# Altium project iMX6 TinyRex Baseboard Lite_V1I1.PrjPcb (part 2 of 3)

## Sheet [07] - PCIE MINI.SchDoc
size A2; DocumentNumber: 7; SheetNumber: 7; SheetTotal: 18
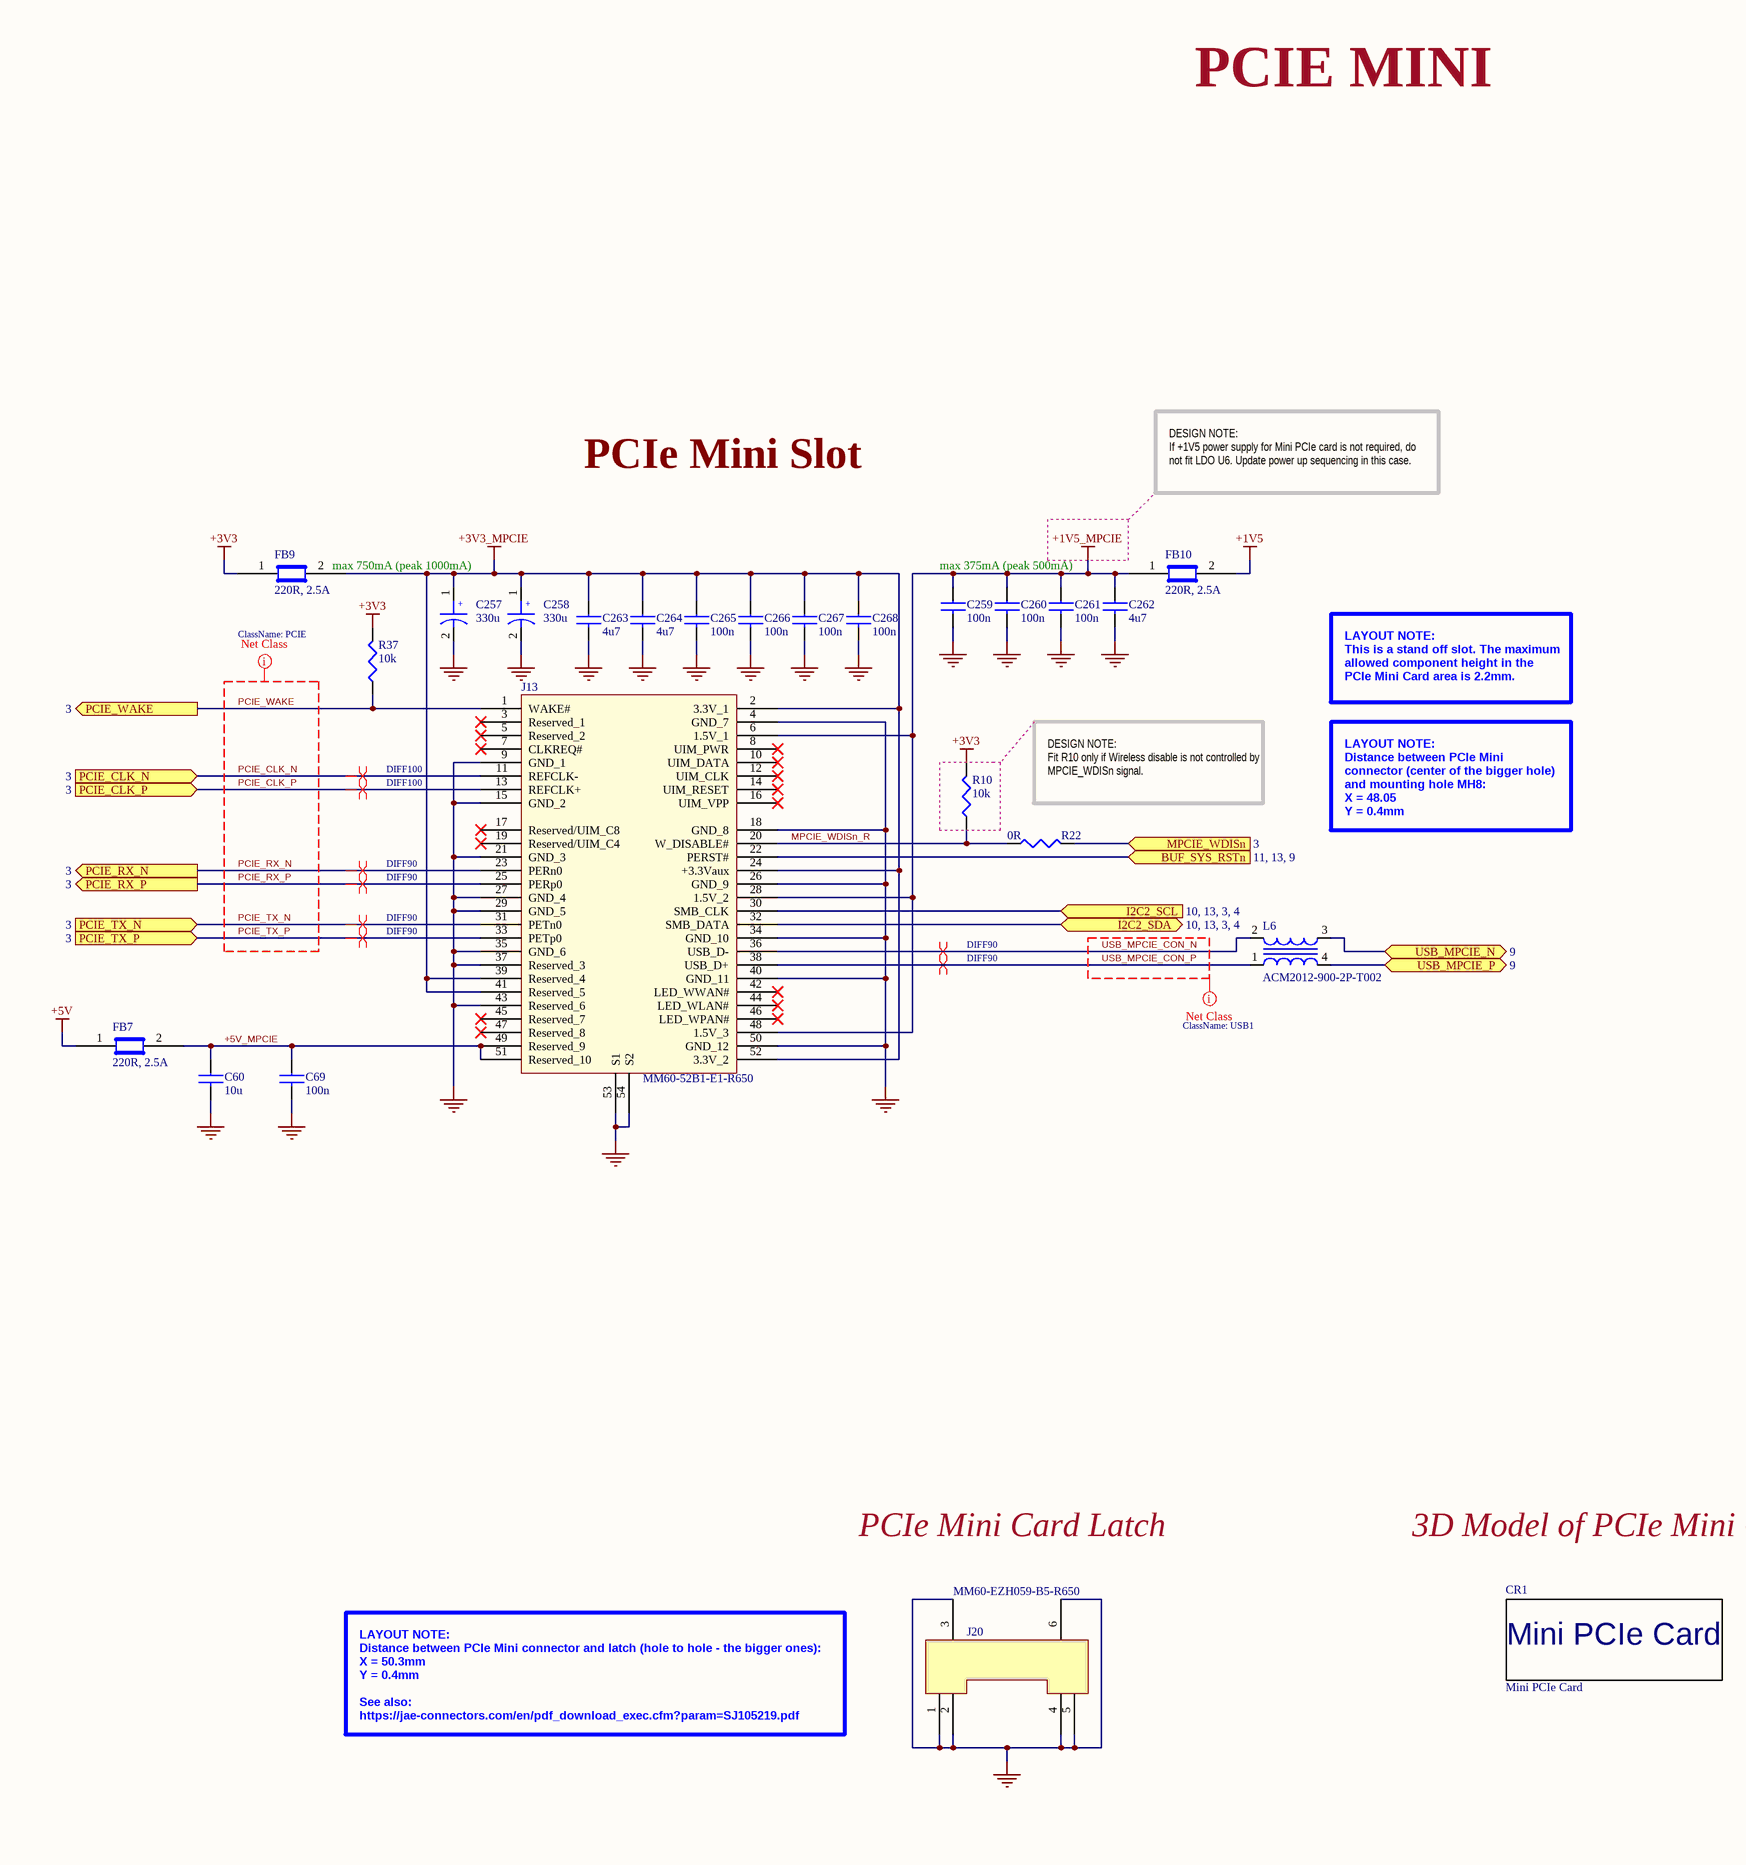
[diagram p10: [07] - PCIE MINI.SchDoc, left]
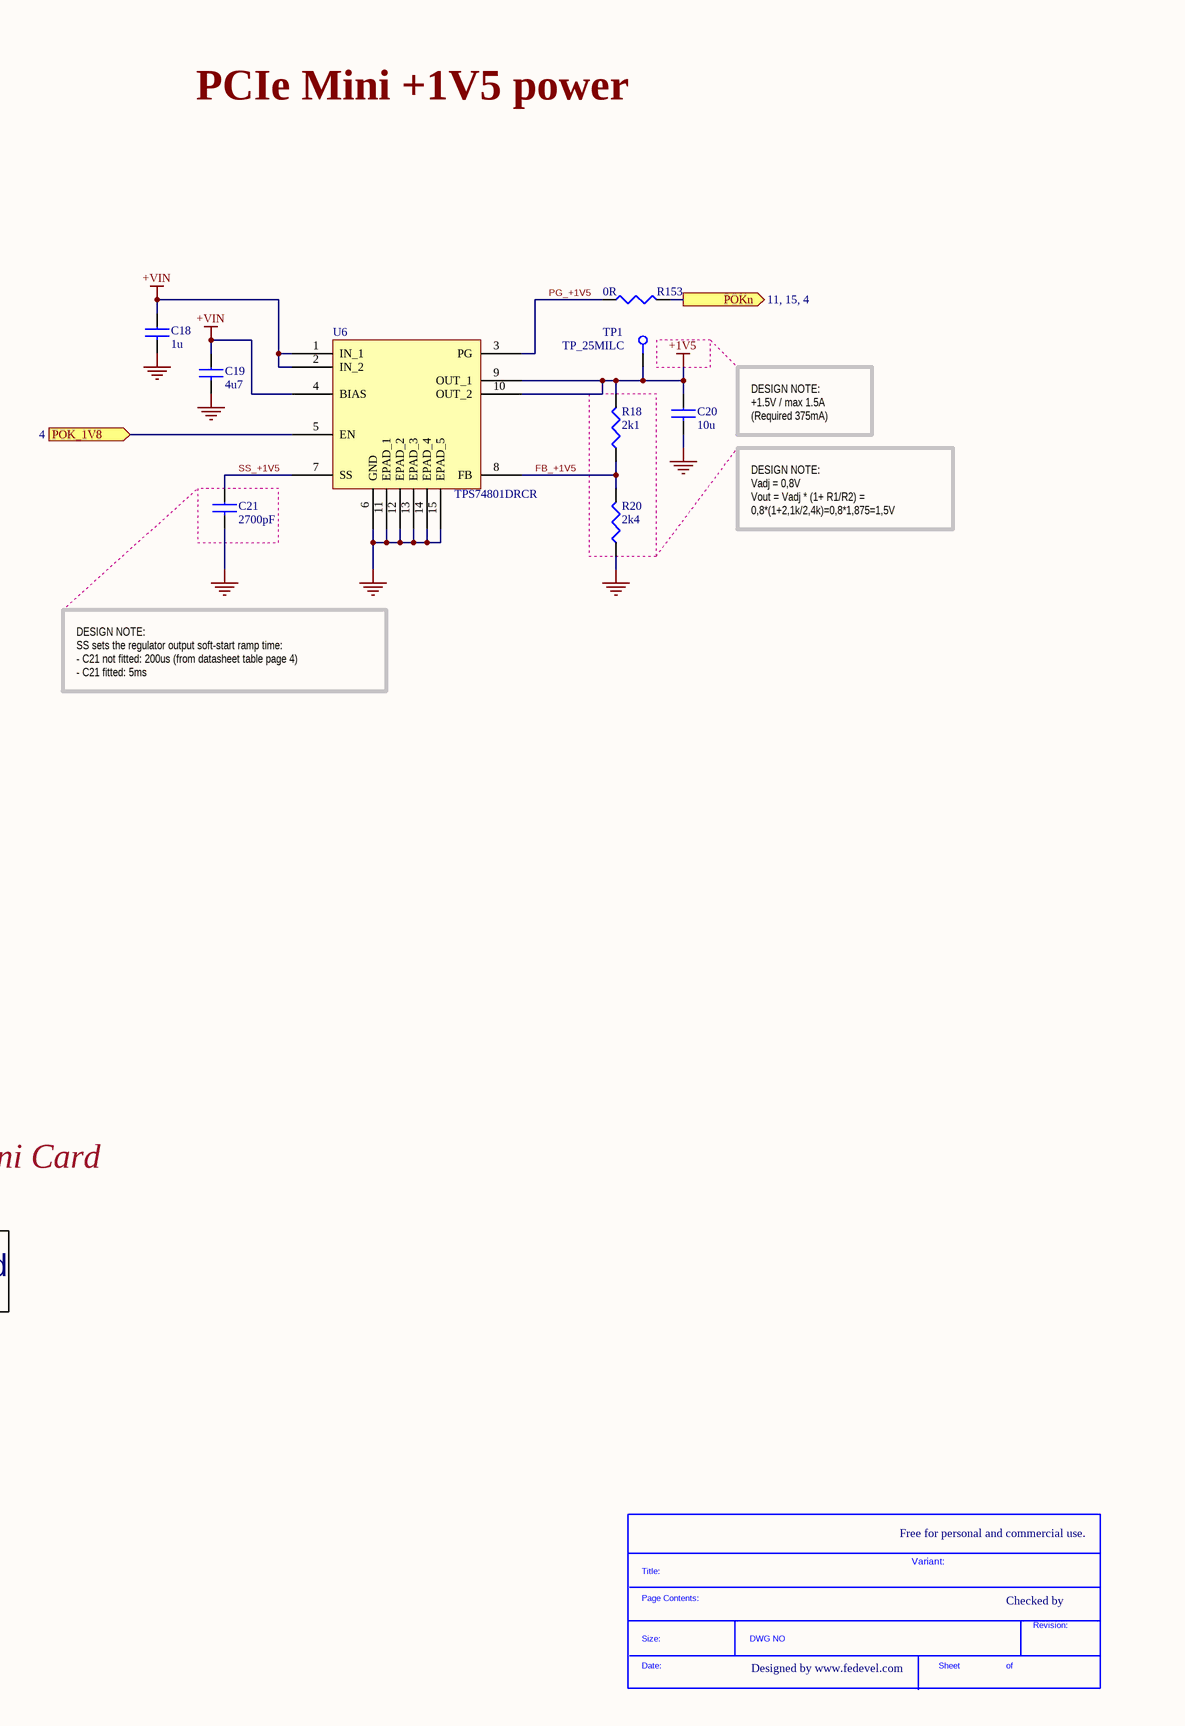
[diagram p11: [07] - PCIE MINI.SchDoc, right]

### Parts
(Parts that share a designator on the sheet are numbered #1, #2 ... from top to bottom, then left to right.)
*#8  SDTitleBlock  (value not drawn)  (graphical)
C18  1u  [C0402]
C19  4u7  [C0402]
C20  10u  [C0603]
C21  2700pF  [C0402]
C60  10u  [C0603]
C69  100n  [C0402]
C257  330u  [C2917]
C258  330u  [C2917]
C259  100n  [C0402]
C260  100n  [C0402]
C261  100n  [C0402]
C262  4u7  [C0402]
C263  4u7  [C0402]
C264  4u7  [C0402]
C265  100n  [C0402]
C266  100n  [C0402]
C267  100n  [C0402]
C268  100n  [C0402]
CR1  Mini PCIe Card  [Mini_PCIe_full card]  (no BOM)
FB7  220R, 2.5A  [C0603]
FB9  220R, 2.5A  [C0603]
FB10  220R, 2.5A  [C0603]
J13  MM60-52B1-E1-R650  [MINI_PCIE_52PIN_CARD_CON]
J20  MM60-EZH059-B5-R650  [MINI_PCIE_52PIN_CARD_LATCH]
L6  ACM2012-900-2P-T002  [ACM2012]
R10  10k  [R0402]
R18  2k1  [R0402]
R20  2k4  [R0402]
R22  0R  [R0402]
R37  10k  [R0402]
R153  0R  [R0402]
TP1  TP_25MILC  [TP_25C]  (no BOM)
U6  TPS74801DRCR  [DRC (S-PVSON-N10)]

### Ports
BUF_SYS_RSTn (see 11, 13, 9), I2C2_SCL (see 10, 13, 3, 4), I2C2_SDA (bidir, see 10, 13, 3, 4), MPCIE_WDISn (in, see 3), PCIE_CLK_N (in, see 3), PCIE_CLK_P (in, see 3), PCIE_RX_N (out, see 3), PCIE_RX_P (out, see 3), PCIE_TX_N (in, see 3), PCIE_TX_P (in, see 3), PCIE_WAKE (out, see 3), POK_1V8 (in, see 4), POKn (see 11, 15, 4), USB_MPCIE_N (bidir, see 9), USB_MPCIE_P (bidir, see 9)

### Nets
+1V5: C20.1 FB10.2 R18.2 TP1.1 U6.9(OUT_1) U6.10(OUT_2)
+1V5_MPCIE: C259.1 C260.1 C261.1 C262.1 FB10.1 J13.6(1.5V_1) J13.28(1.5V_2) J13.48(1.5V_3)
+3V3: FB9.1 R10.2 R37.2
+3V3_MPCIE: C257.1 C258.1 C263.1 C264.1 C265.1 C266.1 C267.1 C268.1 FB9.2 J13.2(3.3V_1) J13.24(+3.3Vaux) J13.39(Reserved_4) J13.41(Reserved_5) J13.52(3.3V_2)
+5V: FB7.1
+VIN: C18.1 C19.1 U6.1(IN_1) U6.2(IN_2) U6.4(BIAS)
GND: C18.2 C19.2 C20.2 C21.2 C60.2 C69.2 C257.2 C258.2 C259.2 C260.2 C261.2 C262.2 C263.2 C264.2 C265.2 C266.2 C267.2 C268.2 J13.4(GND_7) J13.9(GND_1) J13.15(GND_2) J13.18(GND_8) J13.21(GND_3) J13.26(GND_9) J13.27(GND_4) J13.29(GND_5) J13.34(GND_10) J13.35(GND_6) J13.37(Reserved_3) J13.40(GND_11) J13.43(Reserved_6) J13.50(GND_12) J13.53(S1) J13.54(S2) J20.1 J20.2 J20.3 J20.4 J20.5 J20.6 R20.1 U6.6(GND) U6.11(EPAD_1) U6.12(EPAD_2) U6.13(EPAD_3) U6.14(EPAD_4) U6.15(EPAD_5)
+5V_MPCIE: C60.1 C69.1 FB7.2 J13.49(Reserved_9) J13.51(Reserved_10)
BUF_SYS_RSTn: J13.22(PERST#) ; port BUF_SYS_RSTn
FB_+1V5: R18.1 R20.2 U6.8(FB)
I2C2_SCL: J13.30(SMB_CLK) ; port I2C2_SCL
I2C2_SDA: J13.32(SMB_DATA) ; port I2C2_SDA
MPCIE_WDISn: R22.2 ; port MPCIE_WDISn
MPCIE_WDISn_R: J13.20(W_DISABLE#) R10.1 R22.1
PCIE_CLK_N: J13.11(REFCLK-) ; port PCIE_CLK_N
PCIE_CLK_P: J13.13(REFCLK+) ; port PCIE_CLK_P
PCIE_RX_N: J13.23(PERn0) ; port PCIE_RX_N
PCIE_RX_P: J13.25(PERp0) ; port PCIE_RX_P
PCIE_TX_N: J13.31(PETn0) ; port PCIE_TX_N
PCIE_TX_P: J13.33(PETp0) ; port PCIE_TX_P
PCIE_WAKE: J13.1(WAKE#) R37.1 ; port PCIE_WAKE
PG_+1V5: R153.1 U6.3(PG)
POK_1V8: U6.5(EN) ; port POK_1V8
POKn: R153.2 ; port POKn
SS_+1V5: C21.1 U6.7(SS)
USB_MPCIE_CON_N: J13.36(USB_D-) L6.2
USB_MPCIE_CON_P: J13.38(USB_D+) L6.1
USB_MPCIE_N: L6.3 ; port USB_MPCIE_N
USB_MPCIE_P: L6.4 ; port USB_MPCIE_P

Not connected (* = marked no-connect by the designer): J13 3(Reserved_1)* 5(Reserved_2)* 7(CLKREQ#)* 8(UIM_PWR)* 10(UIM_DATA)* 12(UIM_CLK)* 14(UIM_RESET)* 16(UIM_VPP)* 17(Reserved/UIM_C8)* 19(Reserved/UIM_C4)* 42(LED_WWAN#)* 44(LED_WLAN#)* 45(Reserved_7)* 46(LED_WPAN#)* 47(Reserved_8)*

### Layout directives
differential pair; net class DIFF90: PCIE_RX_N, PCIE_RX_P, PCIE_TX_N, PCIE_TX_P, USB_MPCIE_CON_N, USB_MPCIE_CON_P
net class USB1: USB_MPCIE_CON_N, USB_MPCIE_CON_P
differential pair; net class DIFF100: PCIE_CLK_N, PCIE_CLK_P
net class PCIE: PCIE_CLK_N, PCIE_CLK_P, PCIE_RX_N, PCIE_RX_P, PCIE_TX_N, PCIE_TX_P, PCIE_WAKE

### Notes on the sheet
- PCIE MINI
- PCIe Mini Slot
- DESIGN NOTE:
  If +1V5 power supply for Mini PCIe card is not required, do not fit LDO U6. Update power up sequencing in this case.
- PCIe Mini +1V5 power
- max 750mA (peak 1000mA)
- max 375mA (peak 500mA)
- LAYOUT NOTE:
  This is a stand off slot. The maximum allowed component height in the PCIe Mini Card area is 2.2mm.
- (near R22) DESIGN NOTE:
  Fit R10 only if Wireless disable is not controlled by MPCIE_WDISn signal.
- LAYOUT NOTE:
  Distance between PCIe Mini connector (center of the bigger hole) and mounting hole MH8:
  X = 48.05
  Y = 0.4mm
- DESIGN NOTE:
  +1.5V / max 1.5A
  (Required 375mA)
- DESIGN NOTE:
  Vadj = 0,8V
  Vout = Vadj * (1+ R1/R2) = 0,8*(1+2,1k/2,4k)=0,8*1,875=1,5V
- DESIGN NOTE:
  SS sets the regulator output soft-start ramp time:
  - C21 not fitted: 200us (from datasheet table page 4)
  - C21 fitted: 5ms
- PCIe Mini Card Latch
- 3D Model of PCIe Mini Card
- LAYOUT NOTE:
  Distance between PCIe Mini connector and latch (hole to hole - the bigger ones):
  X = 50.3mm
  Y = 0.4mm
  See also:
  https://jae-connectors.com/en/pdf_download_exec.cfm?param=SJ105219.pdf
- Free for personal and commercial use.
- Variant:
- Checked by
- Designed by www.fedevel.com

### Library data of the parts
C18 = C1005X5R1C105K: CAP CER 1.0UF 16V X5R 0402; Manufacturer: TDK Corporation; Capacitance: 1.0µF; Value: 1uF; .Checked PCB: used; Tolerance: ±10%
C19 C262-C264 = C1005X5R1A475M: CAP CER 4.7UF 10V 20% X5R 0402; Manufacturer: TDK Corporation; Capacitance: 4.7µF; .Checked PCB: used
C20 C60 = C1608X5R0J106M: CAP CER 10UF 6.3V X5R 20% 0603; Manufacturer: TDK Corporation; Capacitance: 10µF; Value: 10µF; .Checked PCB: used
C21 = GRM155R71H272KA01D: CAP CER 2700PF 50V 10% X7R 0402; Manufacturer: Murata Electronics North America; .Checked PCB: used
C69 C259-C261 C265-C268 = C1005X5R1H104K: CAP CER .10UF 50V X5R 10% 0402; Manufacturer: TDK Corporation; Capacitance: 0.1µF; Value: 100nF; .Checked PCB: used
C257 C258 = T520D337M006ATE045: CAP TANT 330UF 6.3V 20% 2917; Manufacturer: Kemet; Manufacturer Size Code: D; Capacitance: 330µF; ESR (Equivalent Series Resistance): 45 mOhm; Type: Molded; .Creator: MM; .Checked PCB: used
CR1 = Card_Mini_PCIe: Card MIni PCIe; .Creator: MM
FB7 FB9 FB10 = BLM18SG221TN1D: FERRITE CHIP 220 OHM 2500MA 0603; Manufacturer: Murata Electronics North America; Impedance @ Frequency: 220 Ohm @ 100MHz; DC Resistance (DCR): 40 mOhm Max; Filter Type: Differential Mode - Single; Number of Lines: 1; .Checked PCB: used
J13 = MM60-52B1-E1-R650: CONN MINI EXPRESS CARD 52POS SMD; Manufacturer: JAE Electronics; Card Type: PCI Express Mini Card; Gender: Female; Number of Positions: 52; Card Thickness: 0.039" (1.00mm); Pitch: 0.031" (0.80mm); Material - Insulation: Thermoplastic; Read Out: Dual; .Creator: MM; .Checked PCB: used
J20 = MM60-EZH059-B5-R650: CONN MINI EXPRESS CARD LATCH SMD; Manufacturer: JAE Electronics; For Use With/Related Products: PCI Express Mini Card; .Creator: MM; .Checked PCB: used
L6 = ACM2012-900-2P-T002: CHOKE COMM MODE 90 OHM .4A SMD; Manufacturer: TDK Corporation; Filter Type: Data, Signal Line; Number of Lines: 2; Current: 400mA; DC Resistance (DCR): 190 mOhm Max; Impedance: 90 Ohm; Resistance (Ohms): 8.2K; Power (Watts): 0.063W, 1/16W; Temperature Coefficient: ±100ppm/°C; Tolerance: ±1%; .Checked PCB: used
R10 R37 = RC0402FR-0710KL: RES 10.0K OHM 1/16W 1% 0402 SMD; Manufacturer: Yageo; Power (Watts): 0.063W, 1/16W; .Checked PCB: used; Temperature Coefficient: ±100ppm/°C
R18 = CRCW04022K10FKED: RES 2.10K OHM 1/16W 1% 0402 SMD; Manufacturer: Vishay Dale; Resistance (Ohms): 2.1k; Power (Watts): 0.063W, 1/16W; Temperature Coefficient: ±100ppm/°C; .Creator: MM; .Checked PCB: used
R20 = CRCW04022K40FKED: RES 2.40K OHM 1/16W 1% 0402 SMD; Manufacturer: Vishay Dale; Resistance (Ohms): 2.4K; Power (Watts): 0.063W, 1/16W; Temperature Coefficient: ±100ppm/°C; .Checked PCB: used
R22 R153 = RC0402JR-070RL: RES 0.0 OHM 1/16W 0402 SMD; Manufacturer: Yageo; Resistance (Ohms): 0.0; Power (Watts): 0.063W, 1/16W; Tolerance: Jumper; .Checked PCB: used
TP1 = TP_25MILC: Test Point 25mil
U6 = TPS74801DRCR: IC REG LDO ADJ 1.5A 10SON; Manufacturer: Texas Instruments; Number of Regulators: 1; Regulator Topology: Positive Adjustable; Voltage - Input: 0.8 V ~ 5.5 V; Voltage - Output: 0.8 V ~ 3.6 V; Voltage - Dropout (Typical): 0.06V @ 1.5A; Current - Output: 1.5A (Max); Current - Limit (Min): 2A; .Creator: MM; .Checked PCB: used

## Sheet [09] - USB.SchDoc
size A2; DocumentNumber: 9; SheetNumber: 9; SheetTotal: 18
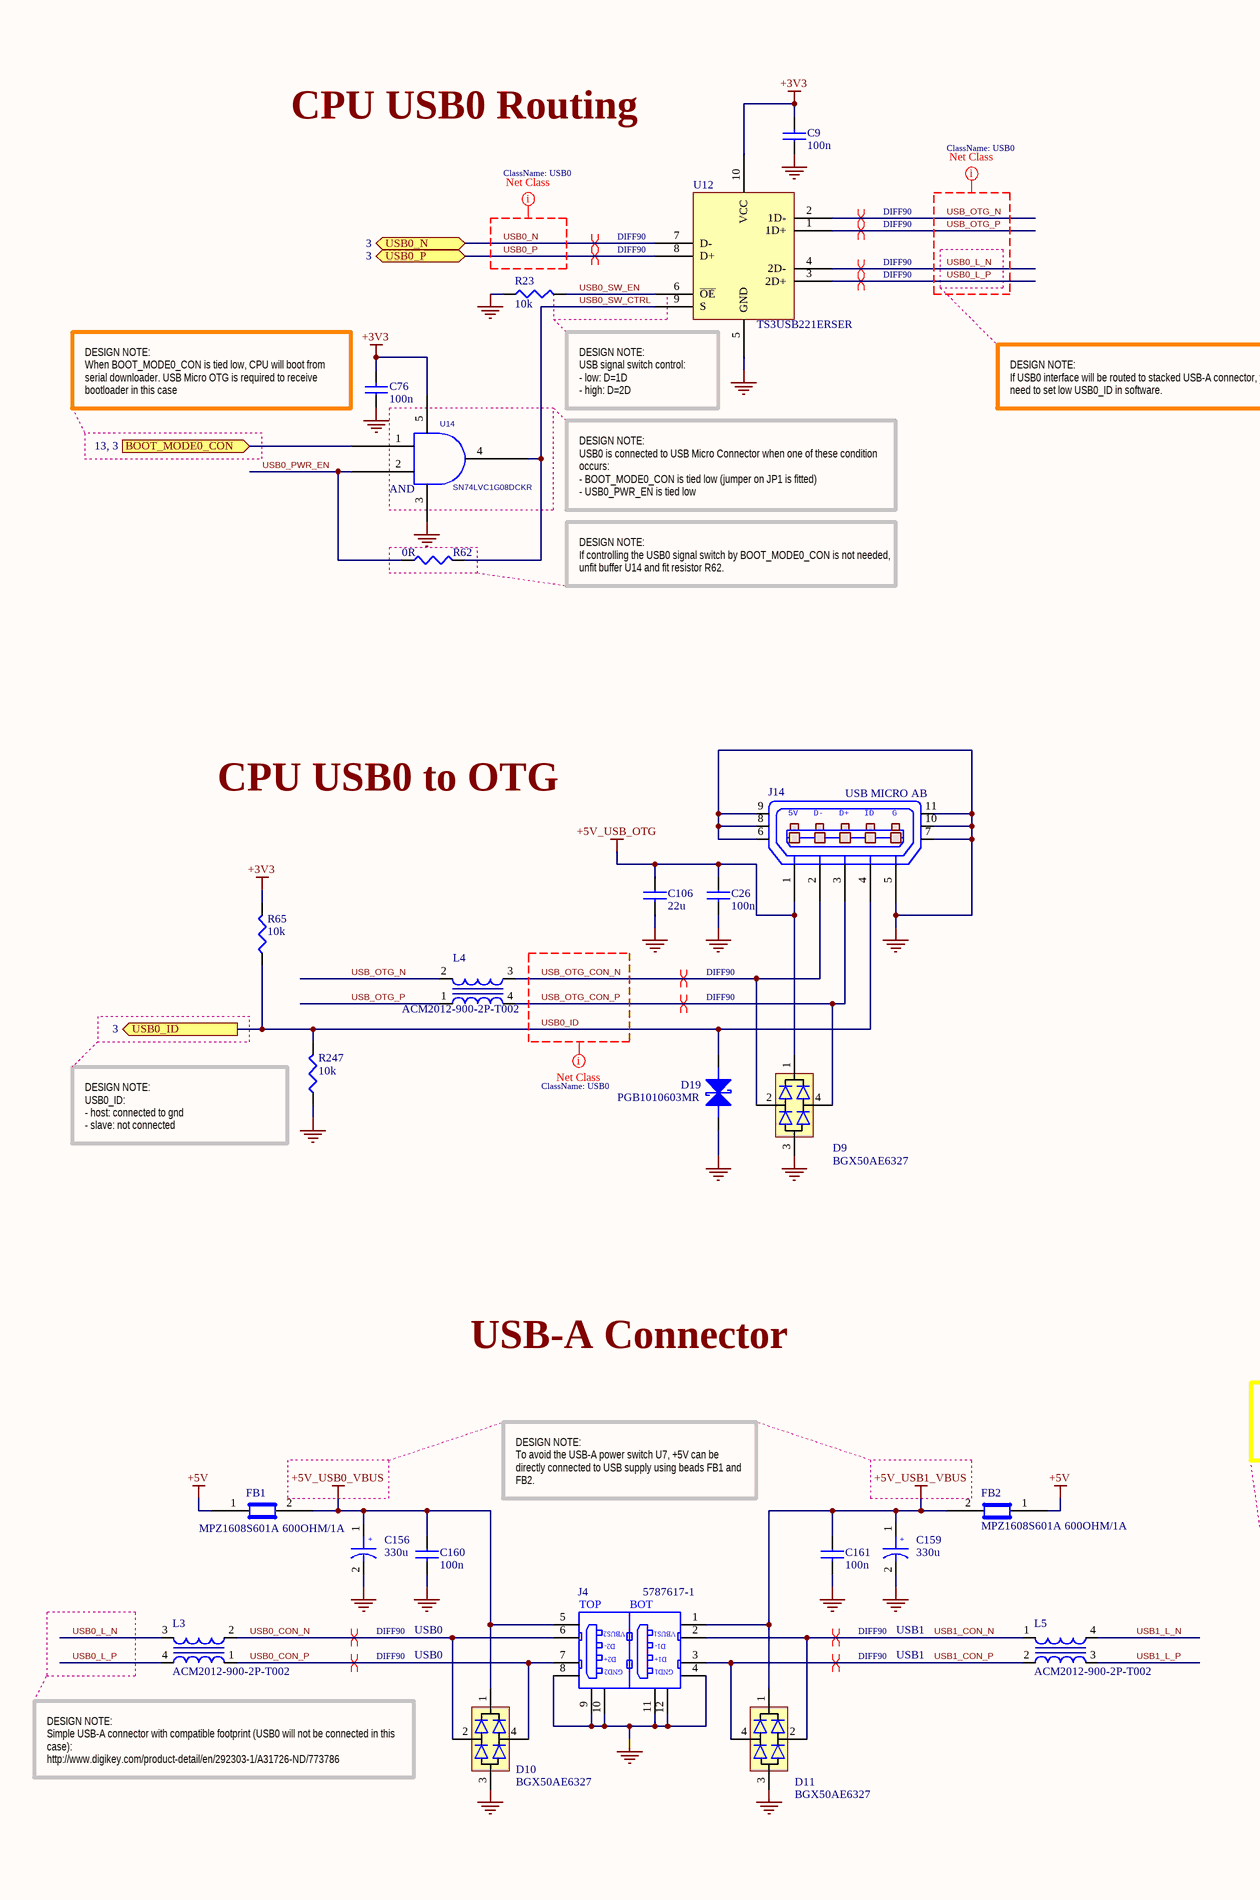
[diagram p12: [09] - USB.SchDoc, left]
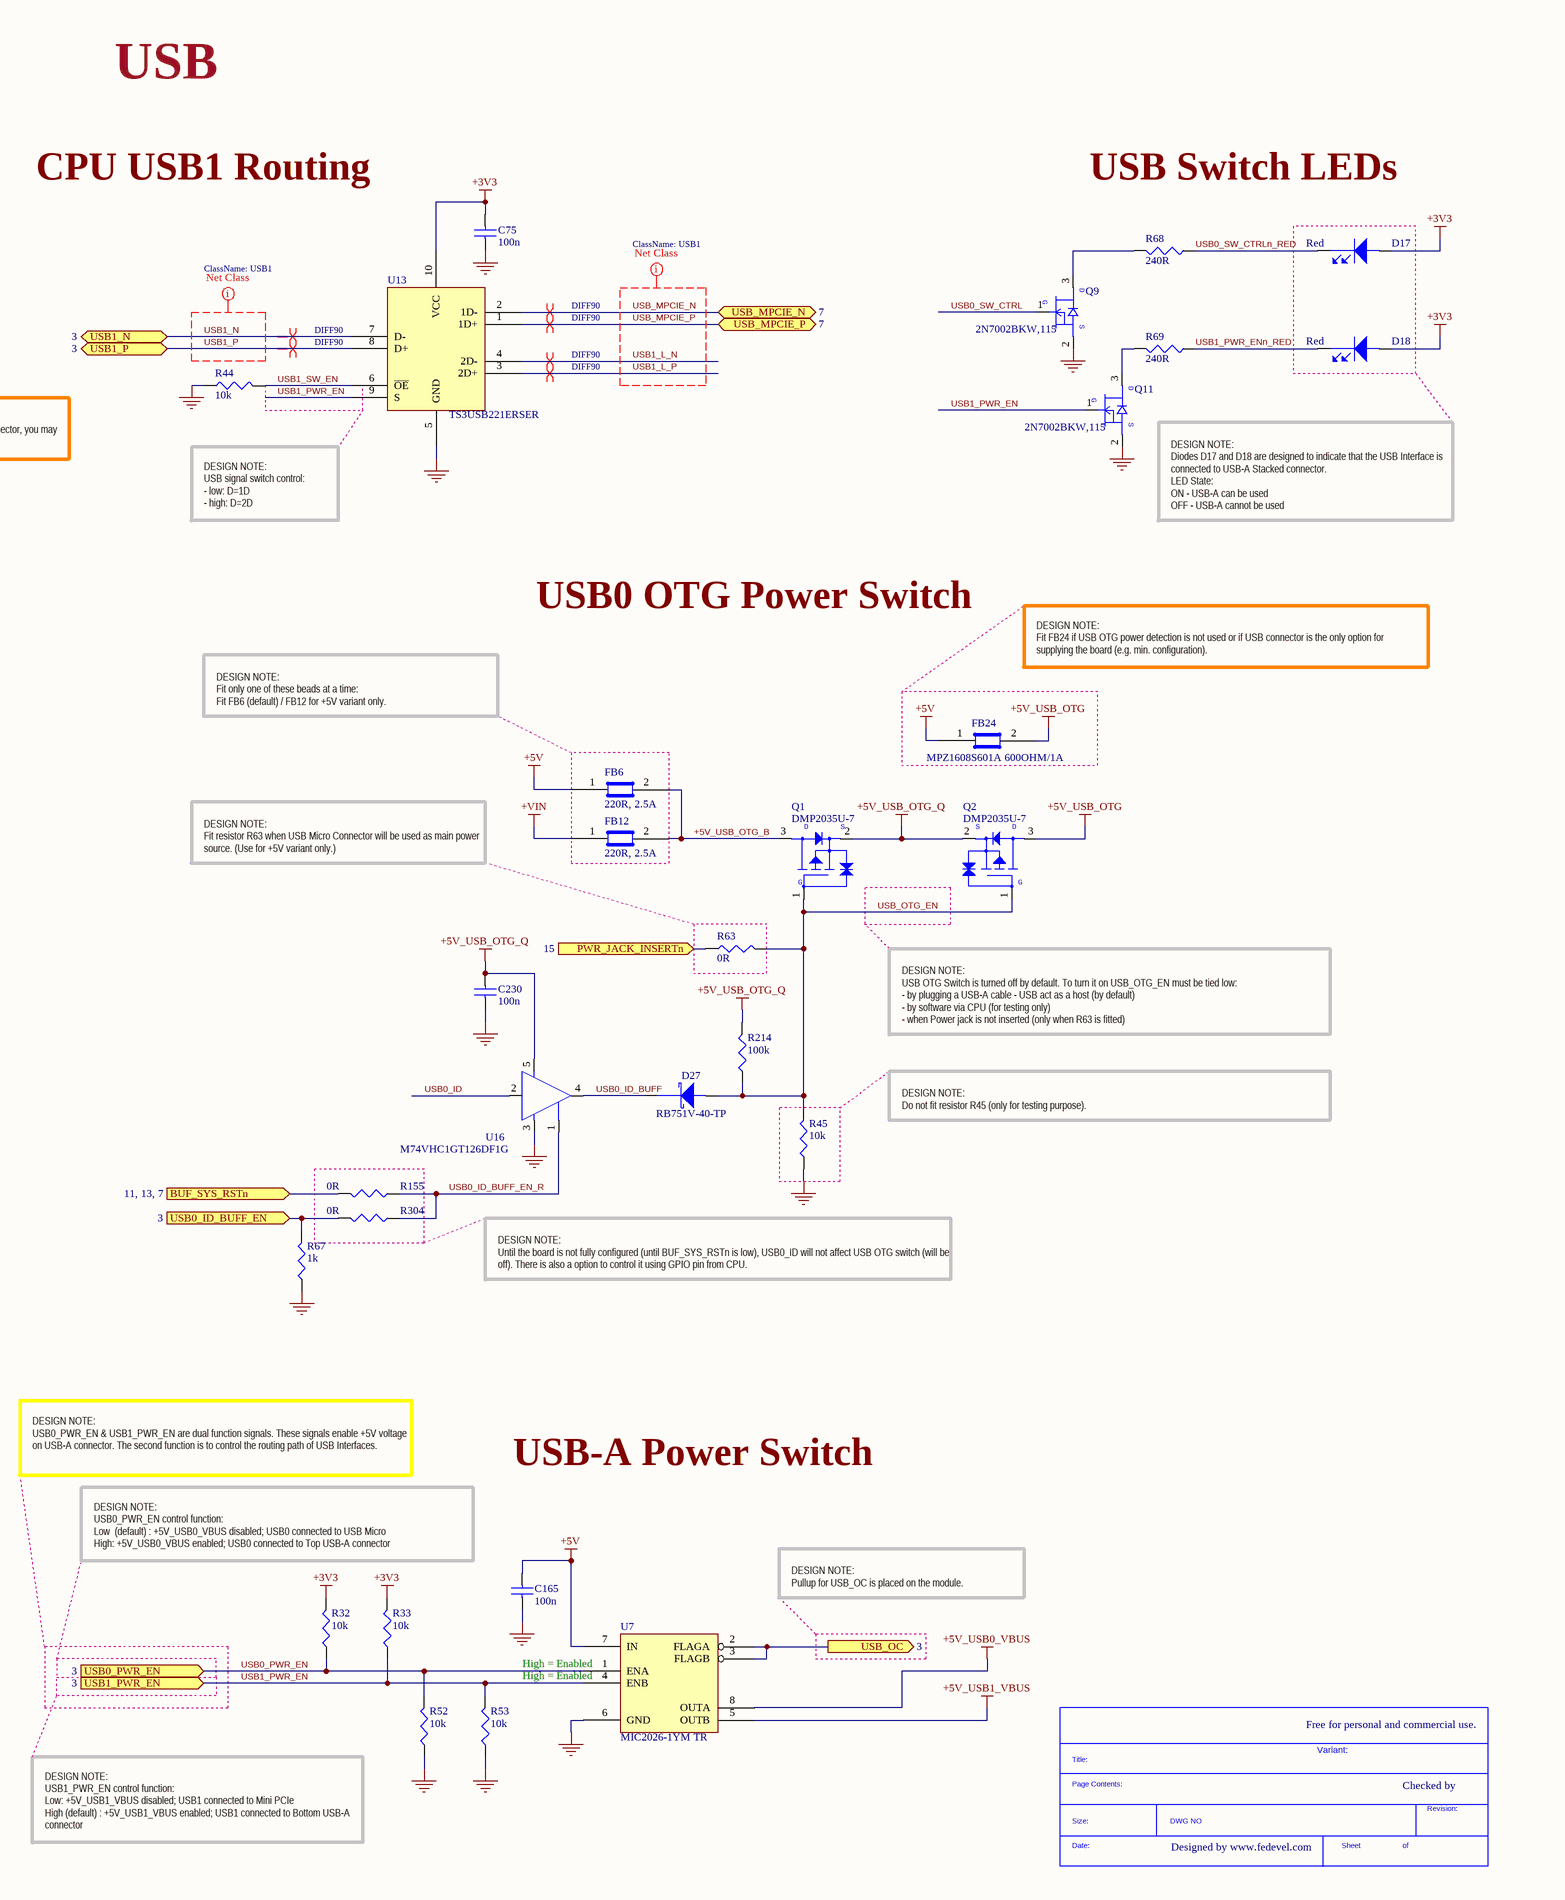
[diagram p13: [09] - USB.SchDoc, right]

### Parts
(Parts that share a designator on the sheet are numbered #1, #2 ... from top to bottom, then left to right.)
*#9  SDTitleBlock  (value not drawn)  (graphical)
C9  100n  [C0402]
C26  100n  [C0402]
C75  100n  [C0402]
C76  100n  [C0402]
C106  22u  [C0805]
C156  330u  [C2917]
C159  330u  [C2917]
C160  100n  [C0402]
C161  100n  [C0402]
C165  100n  [C0402]
C230  100n  [C0402]
D9  BGX50AE6327  [SOT143]
D10  BGX50AE6327  [SOT143]
D11  BGX50AE6327  [SOT143]
D17  Red  [LED_0603]
D18  Red  [LED_0603]
D19  PGB1010603MR  [C0603]
D27  RB751V-40-TP  [SOD323]
FB1  MPZ1608S601A 600OHM/1A  [C0603]
FB2  MPZ1608S601A 600OHM/1A  [C0603]
FB6  220R, 2.5A  [C0603]
FB12  220R, 2.5A  [C0603]
FB24  MPZ1608S601A 600OHM/1A  [C0603]
J4  5787617-1  [USB-2A]
J14  USB MICRO AB  [USB_Micro_AB]
L3  ACM2012-900-2P-T002  [ACM2012]
L4  ACM2012-900-2P-T002  [ACM2012]
L5  ACM2012-900-2P-T002  [ACM2012]
Q1  DMP2035U-7  [SOT-23-3-123]
Q2  DMP2035U-7  [SOT-23-3-123]
Q9  2N7002BKW,115  [SC70_SOT323]
Q11  2N7002BKW,115  [SC70_SOT323]
R23  10k  [R0402]
R32  10k  [R0402]
R33  10k  [R0402]
R44  10k  [R0402]
R45  10k  [R0402]
R52  10k  [R0402]
R53  10k  [R0402]
R62  0R  [R0402]
R63  0R  [R0402]
R65  10k  [R0402]
R67  1k  [R0402]
R68  240R  [R0402]
R69  240R  [R0402]
R155  0R  [R0402]
R214  100k  [R0402]
R247  10k  [R0402]
R304  0R  [R0402]
U7  MIC2026-1YM TR  [8_SOIC_3.9MM]
U12  TS3USB221ERSER  [RSE (R-PUQFN-N10)]
U13  TS3USB221ERSER  [RSE (R-PUQFN-N10)]
U14  SN74LVC1G08DCKR  [SC70_5]
U16  M74VHC1GT126DF1G  [SC70_5]

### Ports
BOOT_MODE0_CON (see 13, 3), BUF_SYS_RSTn (see 11, 13, 7), PWR_JACK_INSERTn (in, see 15), USB0_ID (out, see 3), USB0_ID_BUFF_EN (in, see 3), USB0_N (bidir, see 3), USB0_P (bidir, see 3), USB0_PWR_EN (in, see 3), USB1_N (bidir, see 3), USB1_P (bidir, see 3), USB1_PWR_EN (in, see 3), USB_MPCIE_N (bidir, see 7), USB_MPCIE_P (bidir, see 7), USB_OC (out, see 3)

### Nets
+3V3: C9.2 C75.2 C76.2 D17.2(ANODE) D18.2(ANODE) R32.2 R33.2 R65.2 U12.10(VCC) U13.10(VCC) U14.5(VCC)
+5V: C165.1 FB1.1 FB2.1 FB6.1 FB24.1 U7.7(IN)
+5V_USB0_VBUS: C156.1 C160.1 D10.1 FB1.2 J4.5(VBUS2) U7.8(OUTA)
+5V_USB1_VBUS: C159.1 C161.1 D11.1 FB2.2 J4.1(VBUS) U7.5(OUTB)
+5V_USB_OTG: C26.1 C106.1 D9.1 FB24.2 J14.1(P1) Q2.3
+5V_USB_OTG_Q: C230.2 Q1.2 Q2.2 R214.2 U16.5(VCC)
+VIN: FB12.1
GND: C9.1 C26.2 C75.1 C76.1 C106.2 C156.2 C159.2 C160.2 C161.2 C165.2 C230.1 D9.3 D10.3 D11.3 D19.2 J4.4(GND) J4.8(GND) J4.9(SHIELD) J4.10(SHIELD) J4.11(SHIELD) J4.12(SHIELD) J14.5(P5) J14.6 J14.7 J14.8 J14.9 J14.10 J14.11 Q9.2(SOURCE) Q11.2(SOURCE) R23.1 R44.1 R45.1 R52.1 R53.1 R67.1 R247.1 U7.6(GND) U12.5(GND) U13.5(GND) U14.3(GND) U16.3(GND)
+5V_USB_OTG_B: FB6.2 FB12.2 Q1.3
BOOT_MODE0_CON: U14.1(A) ; port BOOT_MODE0_CON
BUF_SYS_RSTn: R155.2 ; port BUF_SYS_RSTn
PWR_JACK_INSERTn: R63.1 ; port PWR_JACK_INSERTn
USB0_CON_N: D10.2 J4.6(D2-) L3.2
USB0_CON_P: D10.4 J4.7(D2+) L3.1
USB0_ID: D19.1 J14.4(P4) R65.1 R247.2 U16.2(I) ; port USB0_ID
USB0_ID_BUFF: D27.1(cathode) U16.4(O)
USB0_ID_BUFF_EN: R67.2 R304.2 ; port USB0_ID_BUFF_EN
USB0_ID_BUFF_EN_R: R155.1 R304.1 U16.1(OE#)
USB0_L_N: L3.3 U12.4(2D-)
USB0_L_P: L3.4 U12.3(2D+)
USB0_N: U12.7(D-) ; port USB0_N
USB0_P: U12.8(D+) ; port USB0_P
USB0_PWR_EN: R32.1 R52.2 R62.1 U7.1(ENA) U14.2(B) ; port USB0_PWR_EN
USB0_SW_CTRL: Q9.1(GATE) R62.2 U12.9(S) U14.4(Y)
USB0_SW_CTRLn_RED: D17.1(cathode) R68.1
USB0_SW_EN: R23.2 U12.6(~{OE})
USB1_CON_N: D11.2 J4.2(D-) L5.1
USB1_CON_P: D11.4 J4.3(D+) L5.2
USB1_L_N: L5.4 U13.4(2D-)
USB1_L_P: L5.3 U13.3(2D+)
USB1_N: U13.7(D-) ; port USB1_N
USB1_P: U13.8(D+) ; port USB1_P
USB1_PWR_EN: Q11.1(GATE) R33.1 R53.2 U7.4(ENB) U13.9(S) ; port USB1_PWR_EN
USB1_PWR_ENn_RED: D18.1(cathode) R69.1
USB1_SW_EN: R44.2 U13.6(~{OE})
USB_MPCIE_N: U13.2(1D-) ; port USB_MPCIE_N
USB_MPCIE_P: U13.1(1D+) ; port USB_MPCIE_P
USB_OC: U7.2(FLAGA) U7.3(FLAGB) ; port USB_OC
USB_OTG_CON_N: D9.2 J14.2(P2) L4.3
USB_OTG_CON_P: D9.4 J14.3(P3) L4.4
USB_OTG_EN: D27.2(ANODE) Q1.1 Q2.1 R45.2 R63.2 R214.1
USB_OTG_N: L4.2 U12.2(1D-)
USB_OTG_P: L4.1 U12.1(1D+)
NetQ9_3: Q9.3(DRAIN) R68.2
NetQ11_3: Q11.3(DRAIN) R69.2

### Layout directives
differential pair; net class DIFF90: USB0_L_N, USB0_L_P, USB0_N, USB0_P, USB1_L_N, USB1_L_P, USB1_N, USB1_P, USB_MPCIE_N, USB_MPCIE_P, USB_OTG_CON_N, USB_OTG_CON_P, USB_OTG_N, USB_OTG_P
net class USB0: USB0_ID, USB0_L_N, USB0_L_P, USB0_N, USB0_P, USB_OTG_CON_N, USB_OTG_CON_P, USB_OTG_N, USB_OTG_P
differential pair; net class DIFF90; net class USB0: USB0_CON_N, USB0_CON_P
differential pair; net class DIFF90; net class USB1: USB1_CON_N, USB1_CON_P
net class USB1: USB1_L_N, USB1_L_P, USB1_N, USB1_P, USB_MPCIE_N, USB_MPCIE_P

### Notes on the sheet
- USB
- CPU USB0 Routing
- CPU USB1 Routing
- USB Switch LEDs
- (near C76) DESIGN NOTE:
  When BOOT_MODE0_CON is tied low, CPU will boot from serial downloader. USB Micro OTG is required to receive bootloader in this case
- (near U12) DESIGN NOTE:
  USB signal switch control:
  - low: D=1D
  - high: D=2D
- DESIGN NOTE:
  If USB0 interface will be routed to stacked USB-A connector, you may need to set low USB0_ID in software.
- DESIGN NOTE:
  USB signal switch control:
  - low: D=1D
  - high: D=2D
- DESIGN NOTE:
  Diodes D17 and D18 are designed to indicate that the USB Interface is connected to USB-A Stacked connector.
  LED State:
  ON - USB-A can be used
  OFF - USB-A cannot be used
- DESIGN NOTE:
  USB0 is connected to USB Micro Connector when one of these condition occurs:
  - BOOT_MODE0_CON is tied low (jumper on JP1 is fitted)
  - USB0_PWR_EN is tied low
- DESIGN NOTE:
  If controlling the USB0 signal switch by BOOT_MODE0_CON is not needed, unfit buffer U14 and fit resistor R62.
- USB0 OTG Power Switch
- DESIGN NOTE:
  Fit FB24 if USB OTG power detection is not used or if USB connector is the only option for supplying the board (e.g. min. configuration).
- DESIGN NOTE:
  Fit only one of these beads at a time:
  Fit FB6 (default) / FB12 for +5V variant only.
- CPU USB0 to OTG
- DESIGN NOTE:
  Fit resistor R63 when USB Micro Connector will be used as main power source. (Use for +5V variant only.)
- DESIGN NOTE:
  USB OTG Switch is turned off by default. To turn it on USB_OTG_EN must be tied low:
  - by plugging a USB-A cable - USB act as a host (by default)
  - by software via CPU (for testing only)
  - when Power jack is not inserted (only when R63 is fitted)
- DESIGN NOTE:
  Do not fit resistor R45 (only for testing purpose).
- (near R247) DESIGN NOTE:
  USB0_ID:
  - host: connected to gnd
  - slave: not connected
- DESIGN NOTE:
  Until the board is not fully configured (until BUF_SYS_RSTn is low), USB0_ID will not affect USB OTG switch (will be off). There is also a option to control it using GPIO pin from CPU.
- USB-A Connector
- DESIGN NOTE:
  USB0_PWR_EN & USB1_PWR_EN are dual function signals. These signals enable +5V voltage on USB-A connector. The second function is to control the routing path of USB Interfaces.
- USB-A Power Switch
- DESIGN NOTE:
  To avoid the USB-A power switch U7, +5V can be directly connected to USB supply using beads FB1 and FB2.
- DESIGN NOTE:
  USB0_PWR_EN control function:
  Low  (default) : +5V_USB0_VBUS disabled; USB0 connected to USB Micro
  High: +5V_USB0_VBUS enabled; USB0 connected to Top USB-A connector
- DESIGN NOTE:
  Pullup for USB_OC is placed on the module.
- (near U7) High = Enabled
- Free for personal and commercial use.
- DESIGN NOTE:
  Simple USB-A connector with compatible footprint (USB0 will not be connected in this case):
  http://www.digikey.com/product-detail/en/292303-1/A31726-ND/773786
- Variant:
- Checked by
- DESIGN NOTE:
  USB1_PWR_EN control function:
  Low: +5V_USB1_VBUS disabled; USB1 connected to Mini PCIe
  High (default) : +5V_USB1_VBUS enabled; USB1 connected to Bottom USB-A connector
- Designed by www.fedevel.com

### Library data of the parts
C9 C26 C75 C76 C160 C161 C165 C230 = C1005X5R1H104K: as C69 on sheet [07] - PCIE MINI
C106 = C2012X5R1C226K: CAP CER 22UF 16V 10% X5R 0805; Manufacturer: TDK Corporation; Capacitance: 22µF; .Checked PCB: RF
C156 C159 = T495D337K010ATE150: CAP TANT 330UF 10V 10% 2917; Manufacturer: Kemet; Manufacturer Size Code: D; Capacitance: 330µF; ESR (Equivalent Series Resistance): 150 mOhm; Type: Molded; .Creator: MM; .Checked PCB: used
D9-D11 = BGX50AE6327: DIODE SWITCHING 50V SOT-143; Manufacturer: Infineon Technologies; .Checked PCB: used; Current - DC Forward (If): 140mA; Diode Type: Single Phase; Speed: Small Signal =< 200mA (Io), Any Speed; Reverse Recovery Time (trr): 6ns
D17 D18 = LS L29K-H1J2-1-Z: LED SMARTLED RED 630NM 0603 SMD; Manufacturer: OSRAM Opto Semiconductors Inc; Millicandela Rating: 4.95mcd; Voltage - Forward (Vf) Typ: 1.8V; Current - Test: 2mA; Wavelength - Peak: 643nm; Viewing Angle: 160°; Lens Type: Diffused; Lens Style/Size: Rectangle with Flat Top, 1.3mm x 0.8mm; Luminous Flux @ Current - Test: 20 mlm; .Checked PCB: used
D19 = PGB1010603MR: SUPPRESSOR ESD 24VDC 0603 SMD; Manufacturer: Littelfuse Inc; Voltage - Reverse Standoff (Typ): 24V; Polarization: Bidirectional; .Creator: MM; .Checked PCB: used
D27 = RB751V-40-TP: DIODE SCHTKY 30MA 30V SOD-323; Manufacturer: Micro Commercial Co; Diode Type: Schottky; Voltage - Forward (Vf) (Max) @ If: 370mV @ 1mA; Speed: Small Signal =< 200mA (Io), Any Speed; Current - Reverse Leakage @ Vr: 500nA @ 30V; Capacitance @ Vr, F: 2pF @ 1V, 1MHz; .Checked PCB: used
FB1 FB2 FB24 = MPZ1608S601A: FERRITE CHIP BEAD 600 OHM SMD 1A; Manufacturer: TDK Corporation; Impedance @ Frequency: 600 Ohm @ 100MHz; DC Resistance (DCR): 150 mOhm Max; Filter Type: Differential Mode - Single; Number of Lines: 1; .Checked PCB: used
FB6 FB12 = BLM18SG221TN1D: as FB7 on sheet [07] - PCIE MINI
J4 = 5787617-1_v1.1: CONN RCPT R/A 4OVER4POS GOLD PCB; Manufacturer: TE Connectivity; .Checked PCB: used; .Checked SCH: MM; Connector Type: USB - A, Stacked; Number of Contacts: 8; Gender: Receptacle; Specifications: USB 2.0
J14 = 0475890001: CONN RCPT MICRO USB AB R/A SMD; Manufacturer: Molex Inc; Connector Type: USB - micro AB; Number of Contacts: 5; Gender: Receptacle; .Creator: MM; .Checked PCB: used
L3-L5 = ACM2012-900-2P-T002: as L6 on sheet [07] - PCIE MINI
Q1 Q2 = DMP2035U-7: MOSFET P-CH 20V 3.6A SOT-23; Manufacturer: Diodes Incorporated; FET Type: MOSFET P-Channel, Metal Oxide; FET Feature: Logic Level Gate; Current - Continuous Drain (Id) @ 25°C: 3.6A (Ta); Rds On (Max) @ Id, Vgs: 35 mOhm @ 4A, 4.5V; Vgs(th) (Max) @ Id: 1V @ 250µA; Gate Charge (Qg) @ Vgs: 15.4nC @ 4.5V; Input Capacitance (Ciss) @ Vds: 1610pF @ 10V; Power - Max: 810mW; .Checked PCB: MM
Q9 Q11 = 2N7002BKW,115: MOSFET N-CH 60V 310MA SOT323; Manufacturer: NXP Semiconductors; FET Type: MOSFET N-Channel, Metal Oxide; FET Feature: Logic Level Gate; Rds On (Max) @ Id, Vgs: 1.6 Ohm @ 500mA, 10V; Vgs(th) (Max) @ Id: 2.1V @ 250µA; Gate Charge (Qg) @ Vgs: 0.6nC @ 4.5V; Input Capacitance (Ciss) @ Vds: 50pF @ 10V; Power - Max: 275mW; .Checked PCB: used
R23 R32 R33 R44 R45 R52 R53 R65 R247 = RC0402FR-0710KL: as R10 on sheet [07] - PCIE MINI
R62 R63 R155 R304 = RC0402JR-070RL: as R22 on sheet [07] - PCIE MINI
R67 = RC0402FR-071KL: RES 1.00K OHM 1/16W 1% 0402 SMD; Manufacturer: Yageo; Power (Watts): 0.063W, 1/16W; .Checked PCB: used; Temperature Coefficient: ±100ppm/°C
R68 R69 = RMCF0402FT240R: RES TF 240 OHM 1% 0.0625W 0402; Manufacturer: Stackpole Electronics Inc; Resistance (Ohms): 240; Power (Watts): 0.063W, 1/16W; .Checked PCB: used; Temperature Coefficient: ±100ppm/°C
R214 = RMCF0402FT100K: RES 100K OHM 1/16W 1% 0402 SMD; Manufacturer: Stackpole Electronics Inc; Power (Watts): 0.063W, 1/16W; .Checked PCB: used; Temperature Coefficient: ±100ppm/°C
U7 = MIC2026-1YM TR: IC SW DISTRIBUTION 2CHAN 8SOIC; Manufacturer: Micrel Inc; .Checked PCB: used; Number of Outputs: 2; Rds (On): 140 mOhm; Internal Switch(s): Yes; Current Limit: 900mA; Voltage - Input: 2.7 V ~ 5.5 V
U12 U13 = TS3USB221ERSER: IC USB SWITCH DUAL 1X2 10-QFN; Manufacturer: Texas Instruments; Circuit: 2 x 2:1; On-State Resistance: 200 mOhm; Voltage Supply Source: Single Supply; Voltage - Supply, Single/Dual (±): 2.3 V ~ 3.6 V; Current - Supply: 30µA; .Creator: MM
U14 = SN74LVC1G08DCKR: SINGLE POSITIVE AND GATE SC-70; Manufacturer: Texas Instruments; .Checked PCB: used; Number of Inputs: 2; Voltage - Supply: 1.65 V ~ 5.5 V; Number of Circuits: 1; Current - Output High, Low: 32mA, 32mA
U16 = M74VHC1GT126DF1G: IC BUFF CMOS LVL/SFTR N-I SOT353; Manufacturer: ON Semiconductor; Logic Type: Buffer/Line Driver, Non-Inverting; Number of Elements: 1; Current - Output High, Low: 8mA, 8mA; Voltage - Supply: 3 V ~ 5.5 V; .Checked PCB: MM

## Sheet [08] - ETHERNET.SchDoc
size A3; DocumentNumber: 8; SheetNumber: 8; SheetTotal: 18
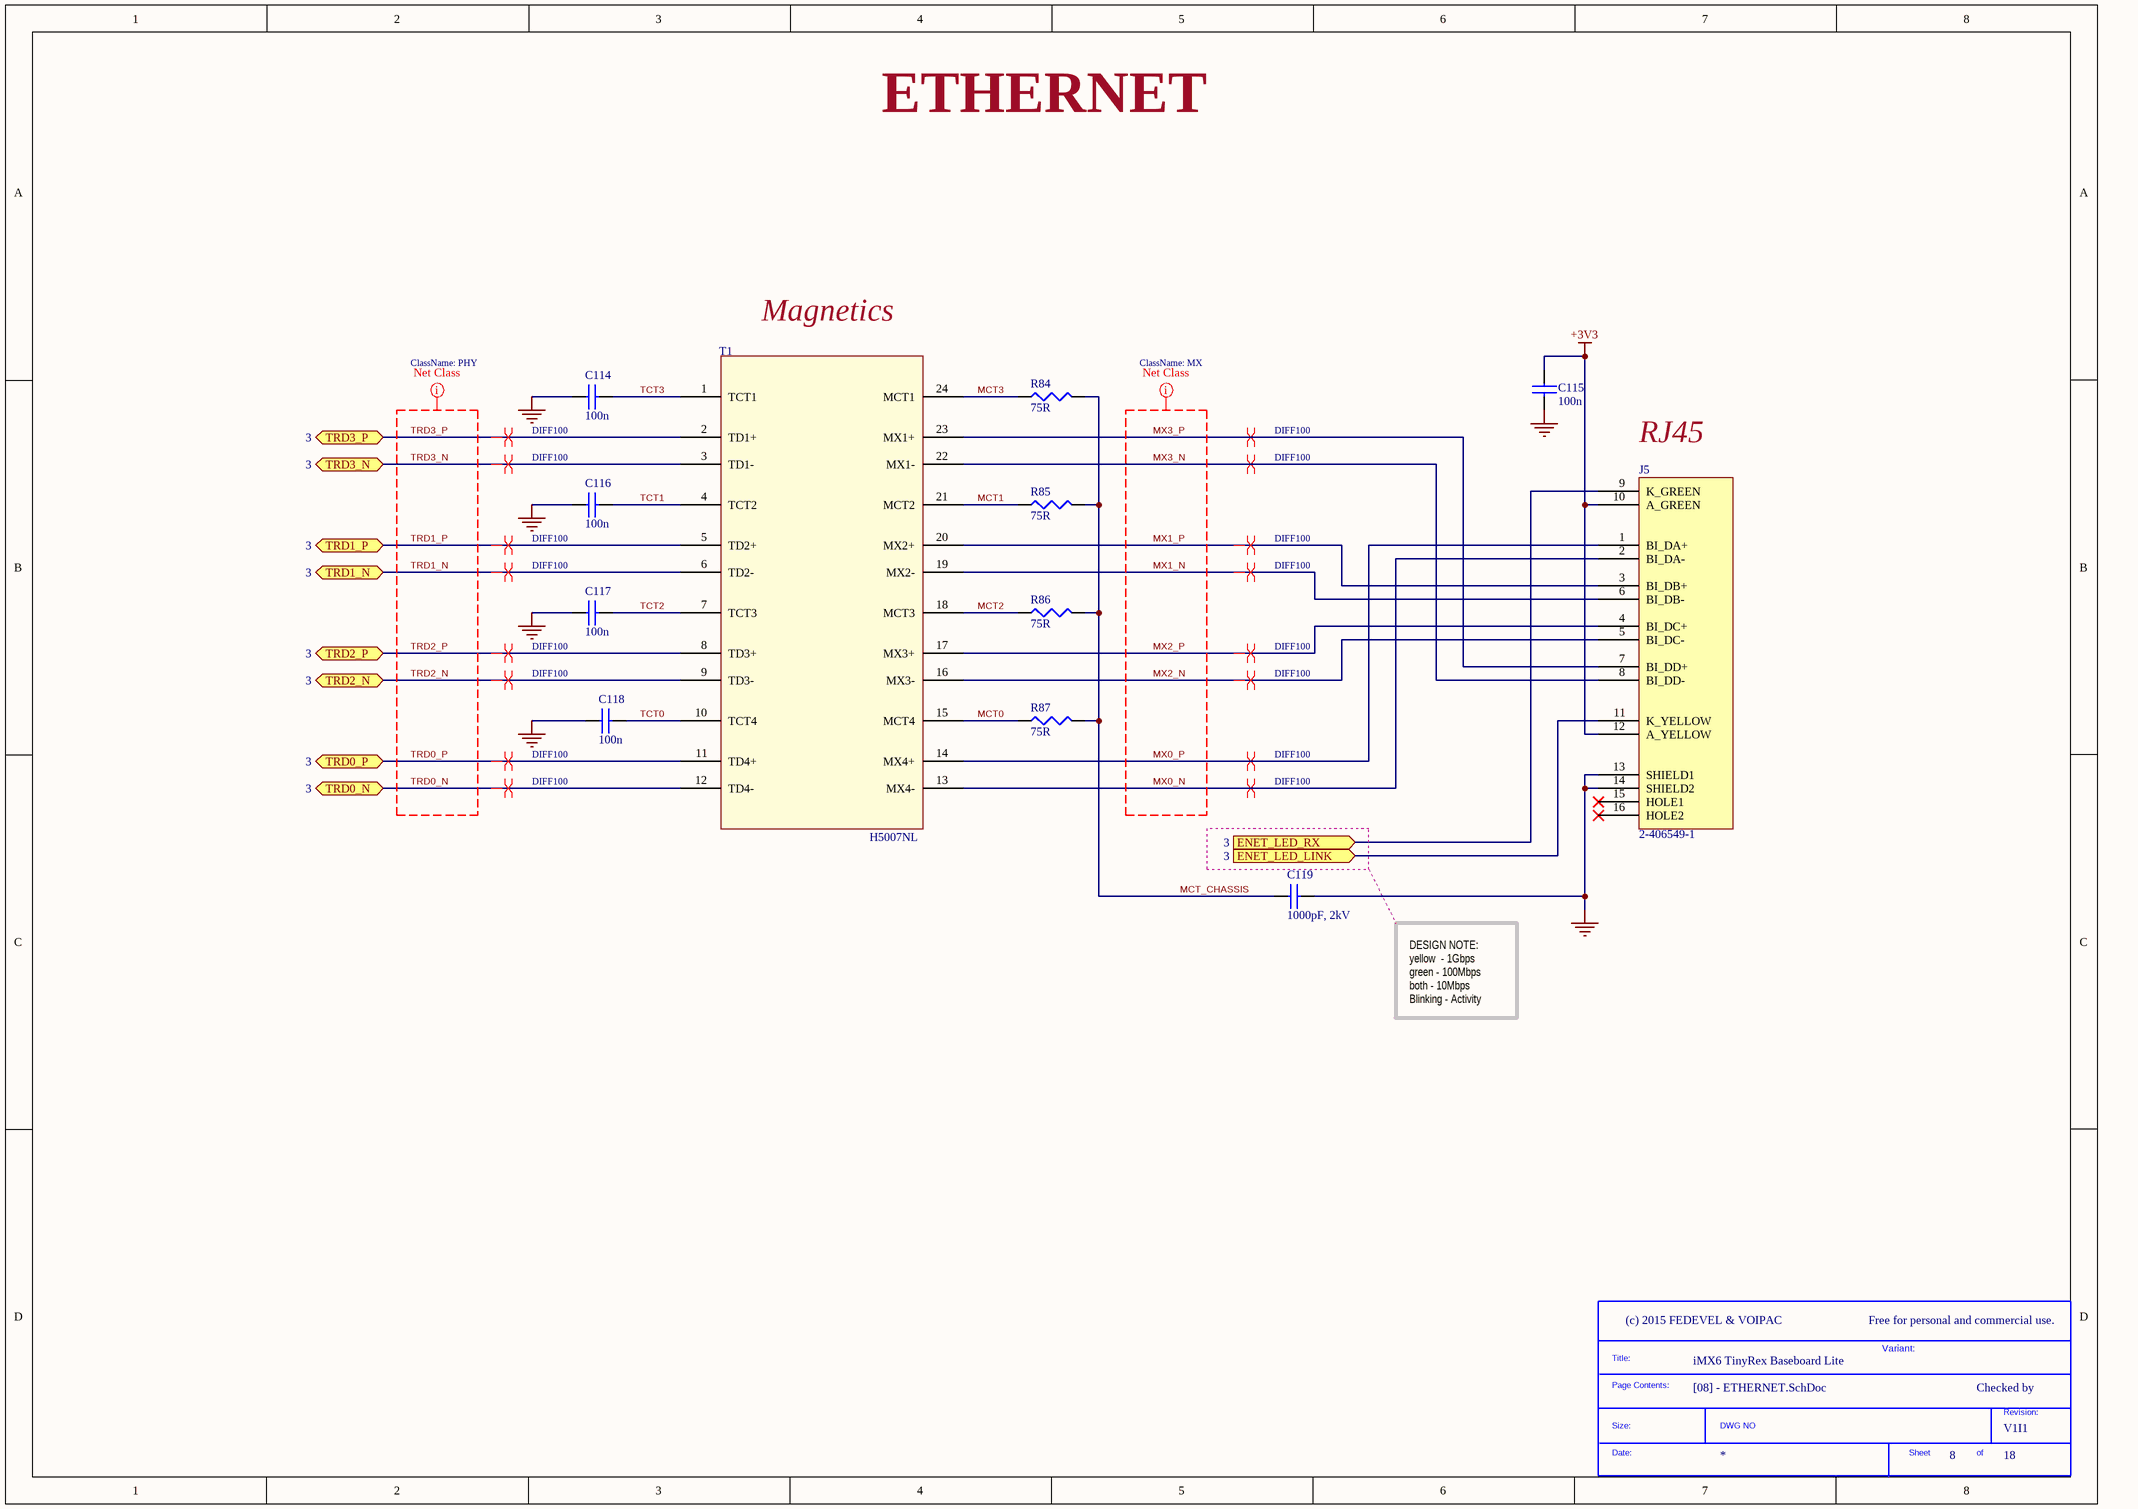
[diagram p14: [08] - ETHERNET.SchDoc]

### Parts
(Parts that share a designator on the sheet are numbered #1, #2 ... from top to bottom, then left to right.)
*#10  SDTitleBlock  (value not drawn)  (graphical)
C114  100n  [C0402]
C115  100n  [C0402]
C116  100n  [C0402]
C117  100n  [C0402]
C118  100n  [C0402]
C119  1000pF, 2kV  [C1206]
J5  2-406549-1  [RJ45LED]
R84  75R  [R0402]
R85  75R  [R0402]
R86  75R  [R0402]
R87  75R  [R0402]
T1  H5007NL  [H5007NL]

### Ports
ENET_LED_LINK (in, see 3), ENET_LED_RX (in, see 3), TRD0_N (bidir, see 3), TRD0_P (bidir, see 3), TRD1_N (bidir, see 3), TRD1_P (bidir, see 3), TRD2_N (bidir, see 3), TRD2_P (bidir, see 3), TRD3_N (bidir, see 3), TRD3_P (bidir, see 3)

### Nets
+3V3: C115.1 J5.10(A_GREEN) J5.12(A_YELLOW)
GND: C114.1 C115.2 C116.1 C117.1 C118.1 C119.2 J5.13(SHIELD1) J5.14(SHIELD2)
ENET_LED_LINK: J5.11(K_YELLOW) ; port ENET_LED_LINK
ENET_LED_RX: J5.9(K_GREEN) ; port ENET_LED_RX
MCT0: R87.1 T1.15(MCT4)
MCT1: R85.1 T1.21(MCT2)
MCT2: R86.1 T1.18(MCT3)
MCT3: R84.1 T1.24(MCT1)
MCT_CHASSIS: C119.1 R84.2 R85.2 R86.2 R87.2
MX0_N: J5.2(BI_DA-) T1.13(MX4-)
MX0_P: J5.1(BI_DA+) T1.14(MX4+)
MX1_N: J5.6(BI_DB-) T1.19(MX2-)
MX1_P: J5.3(BI_DB+) T1.20(MX2+)
MX2_N: J5.5(BI_DC-) T1.16(MX3-)
MX2_P: J5.4(BI_DC+) T1.17(MX3+)
MX3_N: J5.8(BI_DD-) T1.22(MX1-)
MX3_P: J5.7(BI_DD+) T1.23(MX1+)
TCT0: C118.2 T1.10(TCT4)
TCT1: C116.2 T1.4(TCT2)
TCT2: C117.2 T1.7(TCT3)
TCT3: C114.2 T1.1(TCT1)
TRD0_N: T1.12(TD4-) ; port TRD0_N
TRD0_P: T1.11(TD4+) ; port TRD0_P
TRD1_N: T1.6(TD2-) ; port TRD1_N
TRD1_P: T1.5(TD2+) ; port TRD1_P
TRD2_N: T1.9(TD3-) ; port TRD2_N
TRD2_P: T1.8(TD3+) ; port TRD2_P
TRD3_N: T1.3(TD1-) ; port TRD3_N
TRD3_P: T1.2(TD1+) ; port TRD3_P

Not connected (* = marked no-connect by the designer): J5 15(HOLE1)* 16(HOLE2)*

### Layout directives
differential pair; net class DIFF100: MX0_N, MX0_P, MX1_N, MX1_P, MX2_N, MX2_P, MX3_N, MX3_P, TRD0_N, TRD0_P, TRD1_N, TRD1_P, TRD2_N, TRD2_P, TRD3_N, TRD3_P
net class PHY: TRD0_N, TRD0_P, TRD1_N, TRD1_P, TRD2_N, TRD2_P, TRD3_N, TRD3_P
net class MX: MX0_N, MX0_P, MX1_N, MX1_P, MX2_N, MX2_P, MX3_N, MX3_P

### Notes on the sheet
- ETHERNET
- Magnetics
- (near J5) RJ45
- DESIGN NOTE:
  yellow  - 1Gbps
  green - 100Mbps
  both - 10Mbps
  Blinking - Activity
- Free for personal and commercial use.
- Variant:
- Checked by

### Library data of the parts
C114-C118 = C1005X5R1H104K: as C69 on sheet [07] - PCIE MINI
C119 = C1206X102KGRACTU: CAP CER 1000PF 2000V X7R 1206 FT; Manufacturer: Kemet; .Checked PCB: used; Voltage - Rated: 2000V (2kV); Tolerance: ±10%
J5 = 2-406549-1: CONN MOD JACK 8POS R/A G-Y PCB; Manufacturer: Tyco; .Checked PCB: used; Number of Positions: 8p8c (RJ45, Ethernet); Number of Ports: 1; Shielding: Shielded, EMI Finger; Ratings: Cat5; LED Color: Yellow - Green; Tab Direction: Up
R84-R87 = RC0402FR-0775RL: RES 75.0 OHM 1/16W 1% 0402 SMD; Manufacturer: Yageo; Resistance (Ohms): 75; Power (Watts): 0.063W, 1/16W; .Checked PCB: used; Temperature Coefficient: ±100ppm/°C
T1 = H5007NL: MODULE SINGLE GIGABIT LAN 24SOIC; Manufacturer: PULSE ELECTRONICS CORPORATION; .Checked PCB: used; Transformer Type: Isolation and Data Interface (Encapsulated); Turns Ratio - Primary:Secondary: 1CT : 1CT

## Sheet [03] - CONNECTORS.SchDoc
size A2; DocumentNumber: 3; SheetNumber: 3; SheetTotal: 18
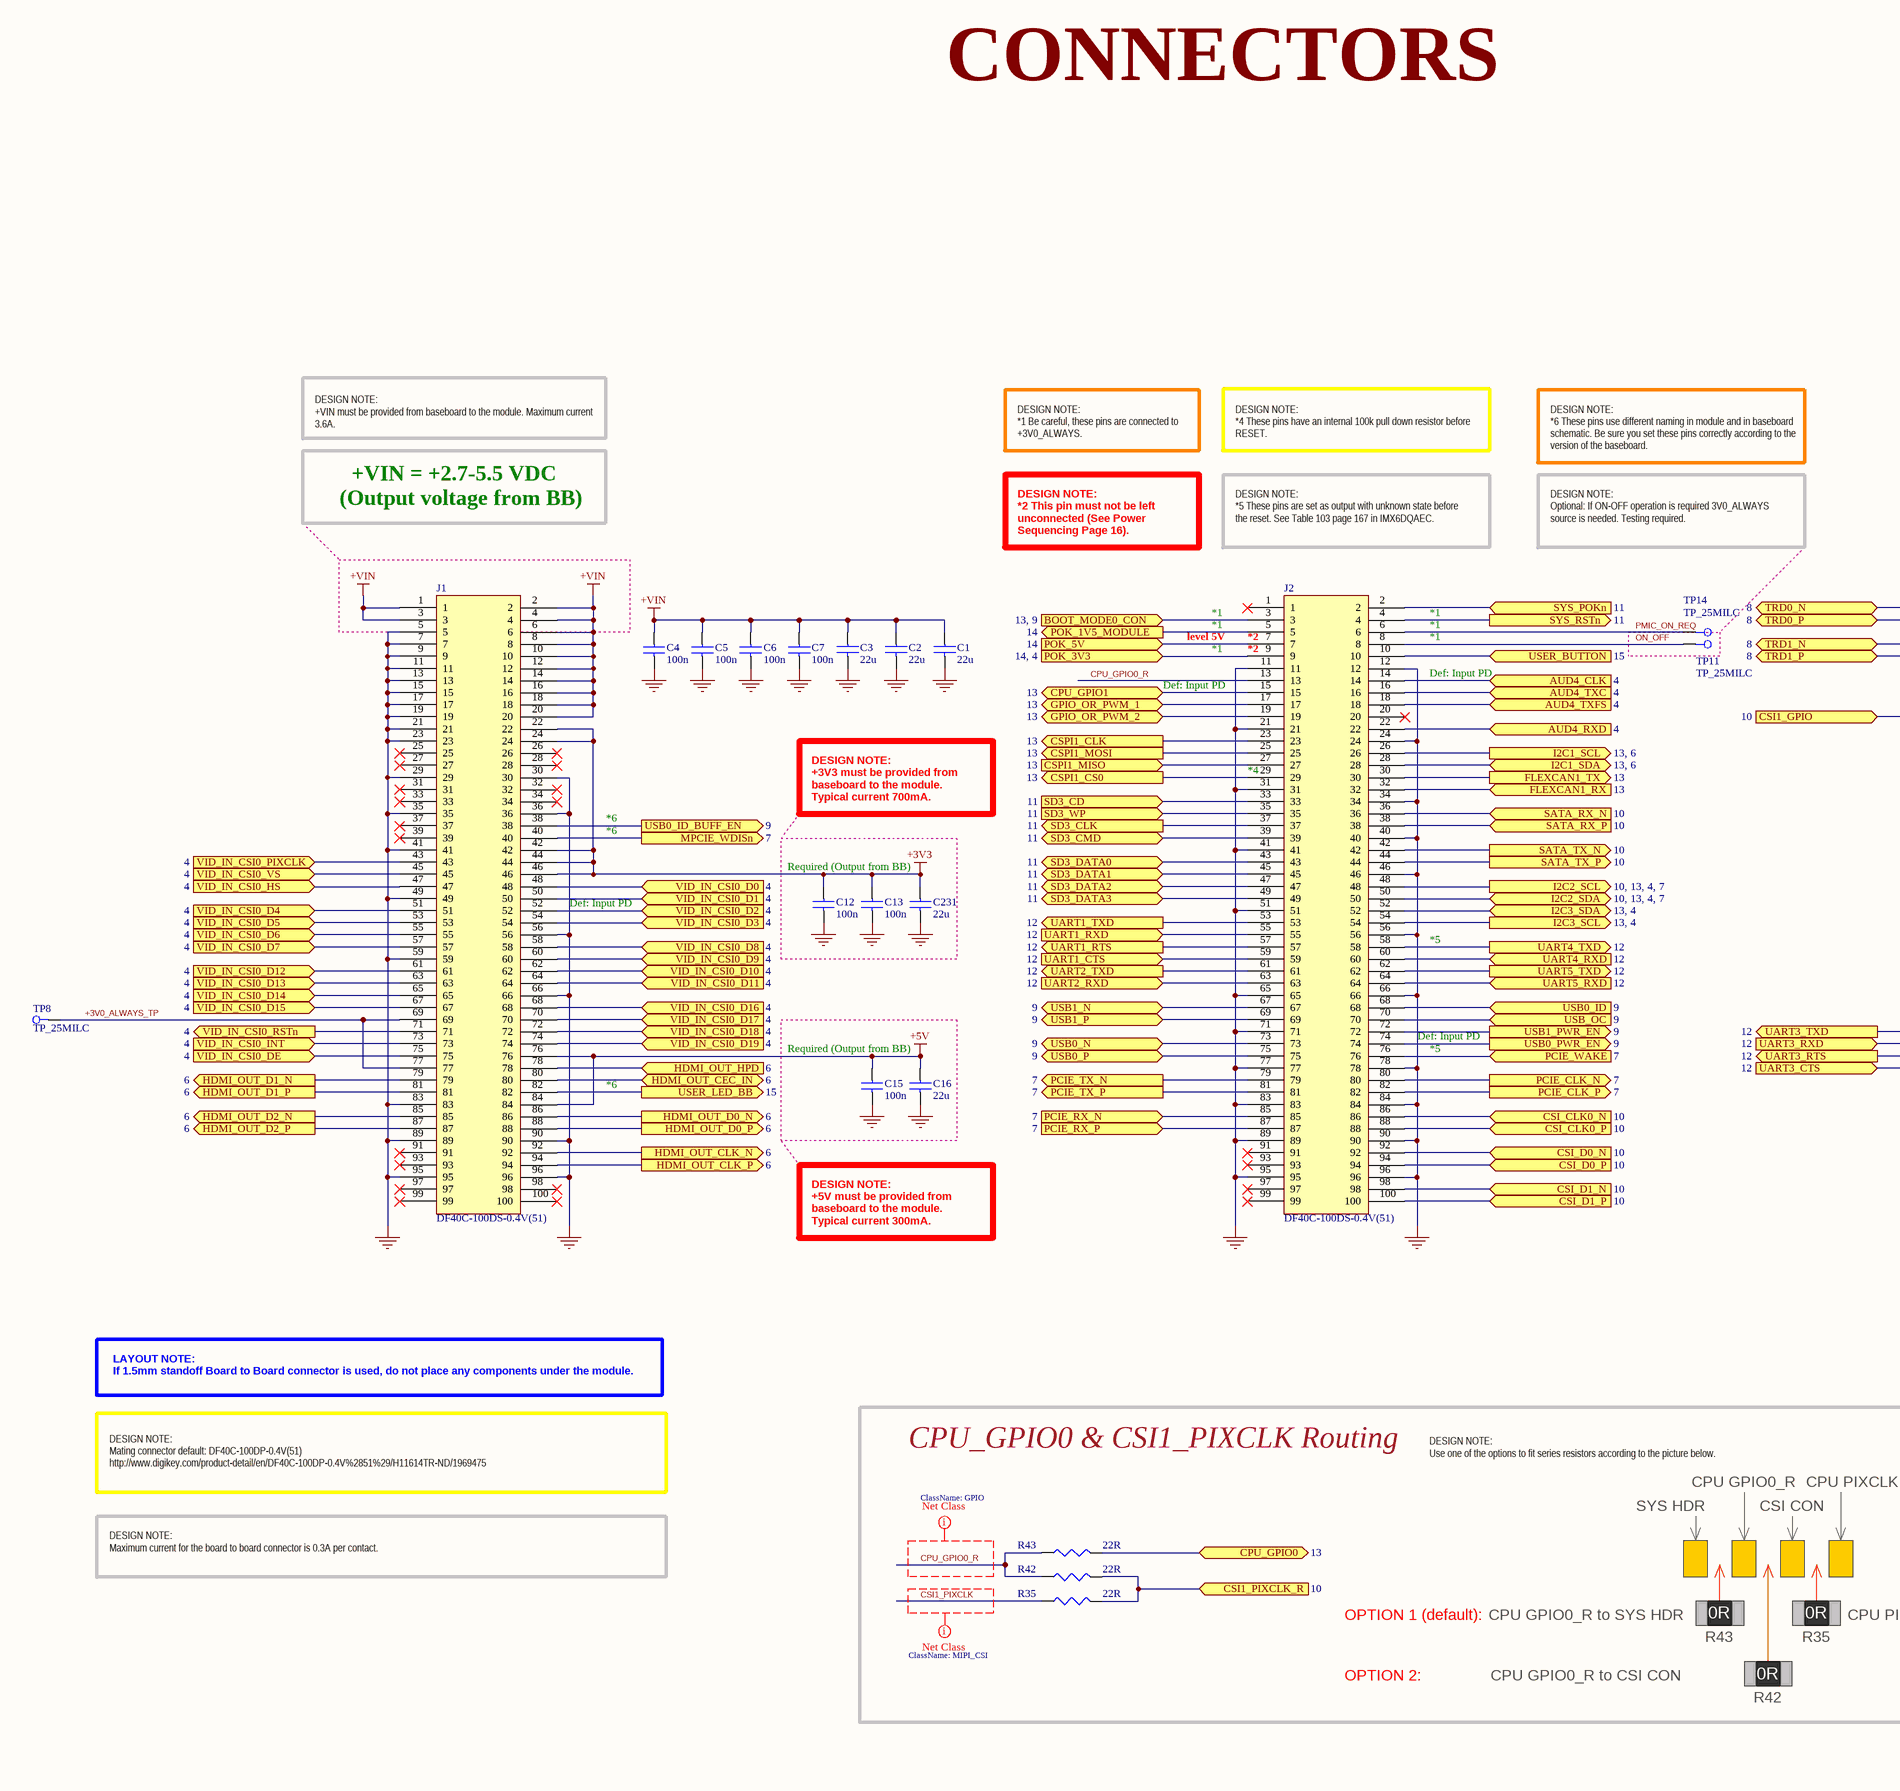
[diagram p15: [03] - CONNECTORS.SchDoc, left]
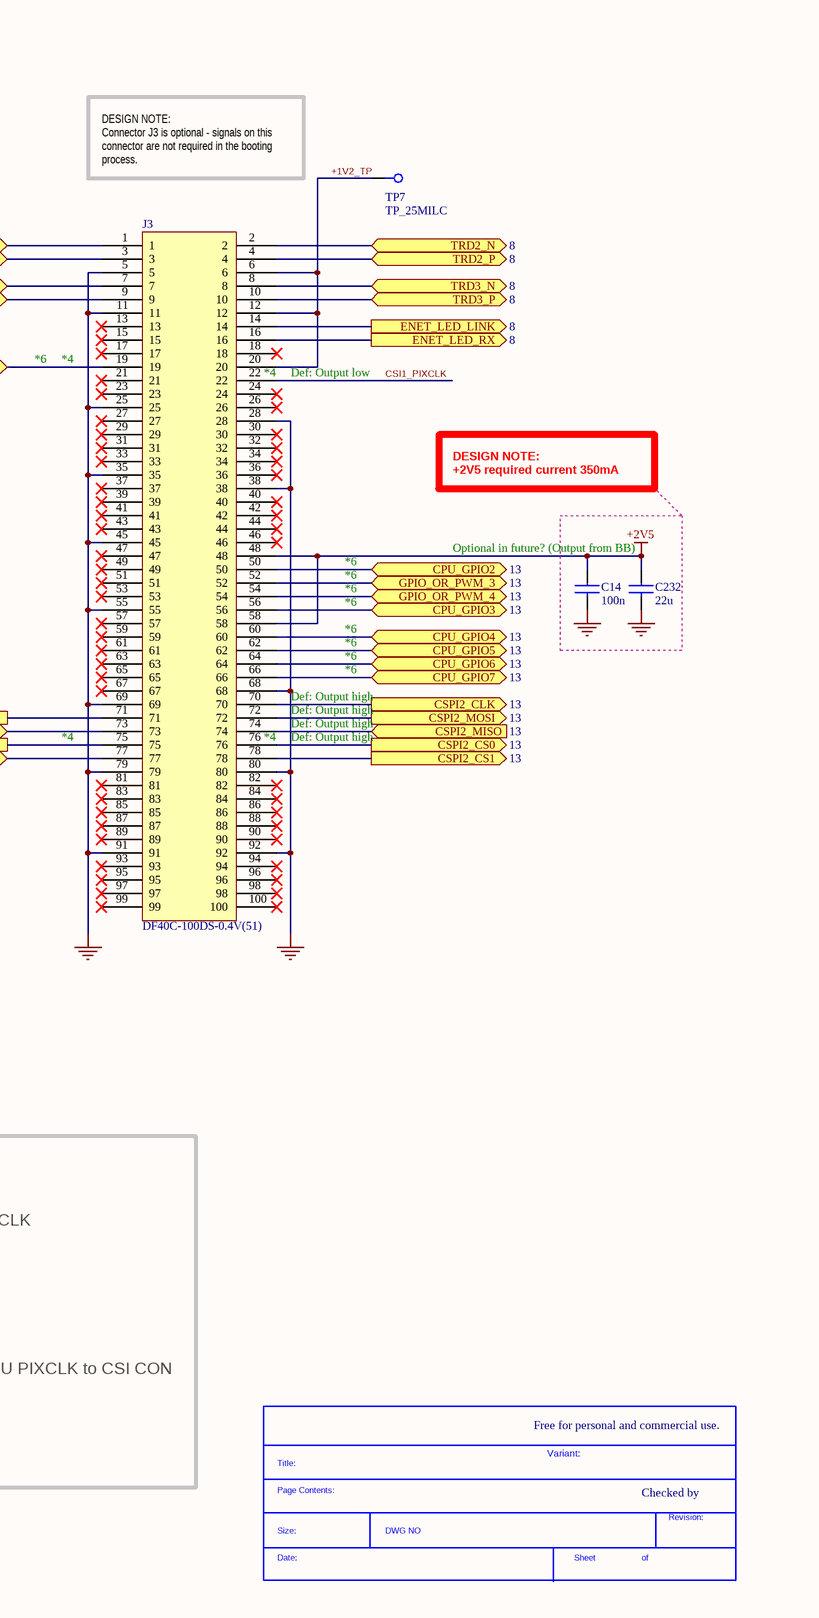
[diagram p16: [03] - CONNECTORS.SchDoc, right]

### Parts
(Parts that share a designator on the sheet are numbered #1, #2 ... from top to bottom, then left to right.)
*#11  SDTitleBlock  (value not drawn)  (graphical)
C1  22u  [C0603]
C2  22u  [C0603]
C3  22u  [C0603]
C4  100n  [C0402]
C5  100n  [C0402]
C6  100n  [C0402]
C7  100n  [C0402]
C12  100n  [C0402]
C13  100n  [C0402]
C14  100n  [C0402]
C15  100n  [C0402]
C16  22u  [C0603]
C231  22u  [C0603]
C232  22u  [C0603]
J1  DF40C-100DS-0.4V(51)  [DF40C-100DS-0.4V(51)_V1.1]
J2  DF40C-100DS-0.4V(51)  [DF40C-100DS-0.4V(51)_V1.1]
J3  DF40C-100DS-0.4V(51)  [DF40C-100DS-0.4V(51)_V1.1]
R35  22R  [R0402]
R42  22R  [R0402]
R43  22R  [R0402]
TP7  TP_25MILC  [TP_25C]  (no BOM)
TP8  TP_25MILC  [TP_25C]  (no BOM)
TP11  TP_25MILC  [TP_25C]  (no BOM)
TP14  TP_25MILC  [TP_25C]  (no BOM)

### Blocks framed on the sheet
Required (Output from BB): C12 C13 C231
Required (Output from BB): C15 C16
CPU_GPIO0 & CSI1_PIXCLK Routing: R35 R42 R43

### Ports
AUD4_CLK (in, see 4), AUD4_RXD (in, see 4), AUD4_TXC (in, see 4), AUD4_TXFS (in, see 4), BOOT_MODE0_CON (see 13, 9), CPU_GPIO0 (bidir, see 13), CPU_GPIO1 (bidir, see 13), CPU_GPIO2 (bidir, see 13), CPU_GPIO3 (bidir, see 13), CPU_GPIO4 (bidir, see 13), CPU_GPIO5 (bidir, see 13), CPU_GPIO6 (bidir, see 13), CPU_GPIO7 (bidir, see 13), CSI1_GPIO (in, see 10), CSI1_PIXCLK_R (in, see 10), CSI_CLK0_N (in, see 10), CSI_CLK0_P (in, see 10), CSI_D0_N (in, see 10), CSI_D0_P (in, see 10), CSI_D1_N (in, see 10), CSI_D1_P (in, see 10), CSPI1_CLK (out, see 13), CSPI1_CS0 (out, see 13), CSPI1_MISO (in, see 13), CSPI1_MOSI (out, see 13), CSPI2_CLK (out, see 13), CSPI2_CS0 (out, see 13), CSPI2_CS1 (out, see 13), CSPI2_MISO (in, see 13), CSPI2_MOSI (out, see 13), ENET_LED_LINK (out, see 8), ENET_LED_RX (out, see 8), FLEXCAN1_RX (in, see 13), FLEXCAN1_TX (out, see 13), GPIO_OR_PWM_1 (bidir, see 13), GPIO_OR_PWM_2 (bidir, see 13), GPIO_OR_PWM_3 (bidir, see 13), GPIO_OR_PWM_4 (bidir, see 13), HDMI_OUT_CEC_IN (bidir, see 6), HDMI_OUT_CLK_N (out, see 6), HDMI_OUT_CLK_P (out, see 6), HDMI_OUT_D0_N (out, see 6), HDMI_OUT_D0_P (out, see 6), HDMI_OUT_D1_N (out, see 6), HDMI_OUT_D1_P (out, see 6), HDMI_OUT_D2_N (out, see 6), HDMI_OUT_D2_P (out, see 6), HDMI_OUT_HPD (in, see 6), I2C1_SCL (see 13, 6), I2C1_SDA (bidir, see 13, 6), I2C2_SCL (see 10, 13, 4, 7), I2C2_SDA (bidir, see 10, 13, 4, 7), I2C3_SCL (see 13, 4), I2C3_SDA (bidir, see 13, 4), MPCIE_WDISn (out, see 7), PCIE_CLK_N (out, see 7), PCIE_CLK_P (out, see 7), PCIE_RX_N (in, see 7), PCIE_RX_P (in, see 7), PCIE_TX_N (out, see 7), PCIE_TX_P (out, see 7), PCIE_WAKE (in, see 7), POK_1V5_MODULE (out, see 14), POK_3V3 (see 14, 4), POK_5V (in, see 14), SATA_RX_N (in, see 10), SATA_RX_P (in, see 10), SATA_TX_N (out, see 10), SATA_TX_P (out, see 10), SD3_CD (in, see 11), SD3_CLK (out, see 11), SD3_CMD (bidir, see 11), SD3_DATA0 (bidir, see 11), SD3_DATA1 (bidir, see 11), SD3_DATA2 (bidir, see 11), SD3_DATA3 (bidir, see 11), SD3_WP (in, see 11), SYS_POKn (in, see 11), SYS_RSTn (out, see 11), TRD0_N (bidir, see 8), TRD0_P (bidir, see 8), TRD1_N (bidir, see 8), TRD1_P (bidir, see 8), TRD2_N (bidir, see 8), TRD2_P (bidir, see 8), TRD3_N (bidir, see 8), TRD3_P (bidir, see 8), UART1_CTS (in, see 12), UART1_RTS (out, see 12), UART1_RXD (in, see 12), UART1_TXD (out, see 12), UART2_RXD (in, see 12), UART2_TXD (out, see 12), UART3_CTS (in, see 12), UART3_RTS (out, see 12), UART3_RXD (in, see 12), UART3_TXD (out, see 12), UART4_RXD (in, see 12), UART4_TXD (out, see 12), UART5_RXD (in, see 12), UART5_TXD (out, see 12), USB0_ID (in, see 9), USB0_ID_BUFF_EN (out, see 9), USB0_N (bidir, see 9), USB0_P (bidir, see 9), USB0_PWR_EN (out, see 9), USB1_N (bidir, see 9), USB1_P (bidir, see 9), USB1_PWR_EN (out, see 9), USB_OC (in, see 9), USER_BUTTON (in, see 15), USER_LED_BB (out, see 15), VID_IN_CSI0_D0 (in, see 4), VID_IN_CSI0_D1 (in, see 4), VID_IN_CSI0_D2 (in, see 4), VID_IN_CSI0_D3 (in, see 4), VID_IN_CSI0_D4 (in, see 4), VID_IN_CSI0_D5 (in, see 4), VID_IN_CSI0_D6 (in, see 4), VID_IN_CSI0_D7 (in, see 4), VID_IN_CSI0_D8 (in, see 4), VID_IN_CSI0_D9 (in, see 4), VID_IN_CSI0_D10 (in, see 4), VID_IN_CSI0_D11 (in, see 4), VID_IN_CSI0_D12 (in, see 4), VID_IN_CSI0_D13 (in, see 4), VID_IN_CSI0_D14 (in, see 4), VID_IN_CSI0_D15 (in, see 4), VID_IN_CSI0_D16 (in, see 4), VID_IN_CSI0_D17 (in, see 4), VID_IN_CSI0_D18 (in, see 4), VID_IN_CSI0_D19 (in, see 4), VID_IN_CSI0_DE (in, see 4), VID_IN_CSI0_HS (in, see 4), VID_IN_CSI0_INT (in, see 4), VID_IN_CSI0_PIXCLK (in, see 4), VID_IN_CSI0_RSTn (out, see 4), VID_IN_CSI0_VS (in, see 4)

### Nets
+2V5: C14.1 C232.1 J3.48 J3.58
+3V3: C12.1 C13.1 C231.1 J1.22 J1.24 J1.42 J1.44 J1.46
+5V: C15.1 C16.1 J1.76 J1.84
+VIN: C1.1 C2.1 C3.1 C4.1 C5.1 C6.1 C7.1 J1.1 J1.2 J1.3 J1.4 J1.6 J1.8 J1.10 J1.12 J1.14 J1.16 J1.18 J1.20
GND: C1.2 C2.2 C3.2 C4.2 C5.2 C6.2 C7.2 C12.2 C13.2 C14.2 C15.2 C16.2 C231.2 C232.2 J1.5 J1.7 J1.9 J1.11 J1.13 J1.15 J1.17 J1.19 J1.21 J1.23 J1.29 J1.30 J1.35 J1.36 J1.41 J1.49 J1.56 J1.59 J1.66 J1.83 J1.89 J1.90 J1.95 J1.96 J2.11 J2.12 J2.21 J2.24 J2.31 J2.34 J2.40 J2.41 J2.46 J2.51 J2.56 J2.65 J2.66 J2.71 J2.77 J2.78 J2.83 J2.84 J2.89 J2.90 J2.95 J2.96 J3.5 J3.11 J3.25 J3.28 J3.35 J3.38 J3.45 J3.55 J3.68 J3.69 J3.79 J3.80 J3.91 J3.92
+1V2_TP: J3.6 J3.12 J3.20 TP7.1
+3V0_ALWAYS_TP: J1.69 J1.77 TP8.1
AUD4_CLK: J2.14 ; port AUD4_CLK
AUD4_RXD: J2.22 ; port AUD4_RXD
AUD4_TXC: J2.16 ; port AUD4_TXC
AUD4_TXFS: J2.18 ; port AUD4_TXFS
BOOT_MODE0_CON: J2.3 ; port BOOT_MODE0_CON
CPU_GPIO0: R43.2 ; port CPU_GPIO0
CPU_GPIO0_R: J2.13 R42.1 R43.1
CPU_GPIO1: J2.15 ; port CPU_GPIO1
CPU_GPIO2: J3.50 ; port CPU_GPIO2
CPU_GPIO3: J3.56 ; port CPU_GPIO3
CPU_GPIO4: J3.60 ; port CPU_GPIO4
CPU_GPIO5: J3.62 ; port CPU_GPIO5
CPU_GPIO6: J3.64 ; port CPU_GPIO6
CPU_GPIO7: J3.66 ; port CPU_GPIO7
CSI1_GPIO: J3.19 ; port CSI1_GPIO
CSI1_PIXCLK: J3.22 R35.1
CSI1_PIXCLK_R: R35.2 R42.2 ; port CSI1_PIXCLK_R
CSI_CLK0_N: J2.86 ; port CSI_CLK0_N
CSI_CLK0_P: J2.88 ; port CSI_CLK0_P
CSI_D0_N: J2.92 ; port CSI_D0_N
CSI_D0_P: J2.94 ; port CSI_D0_P
CSI_D1_N: J2.98 ; port CSI_D1_N
CSI_D1_P: J2.100 ; port CSI_D1_P
CSPI1_CLK: J2.23 ; port CSPI1_CLK
CSPI1_CS0: J2.29 ; port CSPI1_CS0
CSPI1_MISO: J2.27 ; port CSPI1_MISO
CSPI1_MOSI: J2.25 ; port CSPI1_MOSI
CSPI2_CLK: J3.70 ; port CSPI2_CLK
CSPI2_CS0: J3.76 ; port CSPI2_CS0
CSPI2_CS1: J3.78 ; port CSPI2_CS1
CSPI2_MISO: J3.74 ; port CSPI2_MISO
CSPI2_MOSI: J3.72 ; port CSPI2_MOSI
ENET_LED_LINK: J3.14 ; port ENET_LED_LINK
ENET_LED_RX: J3.16 ; port ENET_LED_RX
FLEXCAN1_RX: J2.32 ; port FLEXCAN1_RX
FLEXCAN1_TX: J2.30 ; port FLEXCAN1_TX
GPIO_OR_PWM_1: J2.17 ; port GPIO_OR_PWM_1
GPIO_OR_PWM_2: J2.19 ; port GPIO_OR_PWM_2
GPIO_OR_PWM_3: J3.52 ; port GPIO_OR_PWM_3
GPIO_OR_PWM_4: J3.54 ; port GPIO_OR_PWM_4
HDMI_OUT_CEC_IN: J1.80 ; port HDMI_OUT_CEC_IN
HDMI_OUT_CLK_N: J1.92 ; port HDMI_OUT_CLK_N
HDMI_OUT_CLK_P: J1.94 ; port HDMI_OUT_CLK_P
HDMI_OUT_D0_N: J1.86 ; port HDMI_OUT_D0_N
HDMI_OUT_D0_P: J1.88 ; port HDMI_OUT_D0_P
HDMI_OUT_D1_N: J1.79 ; port HDMI_OUT_D1_N
HDMI_OUT_D1_P: J1.81 ; port HDMI_OUT_D1_P
HDMI_OUT_D2_N: J1.85 ; port HDMI_OUT_D2_N
HDMI_OUT_D2_P: J1.87 ; port HDMI_OUT_D2_P
HDMI_OUT_HPD: J1.78 ; port HDMI_OUT_HPD
I2C1_SCL: J2.26 ; port I2C1_SCL
I2C1_SDA: J2.28 ; port I2C1_SDA
I2C2_SCL: J2.48 ; port I2C2_SCL
I2C2_SDA: J2.50 ; port I2C2_SDA
I2C3_SCL: J2.54 ; port I2C3_SCL
I2C3_SDA: J2.52 ; port I2C3_SDA
MPCIE_WDISn: J1.40 ; port MPCIE_WDISn
ON_OFF: J2.8 TP11.1
PCIE_CLK_N: J2.80 ; port PCIE_CLK_N
PCIE_CLK_P: J2.82 ; port PCIE_CLK_P
PCIE_RX_N: J2.85 ; port PCIE_RX_N
PCIE_RX_P: J2.87 ; port PCIE_RX_P
PCIE_TX_N: J2.79 ; port PCIE_TX_N
PCIE_TX_P: J2.81 ; port PCIE_TX_P
PCIE_WAKE: J2.76 ; port PCIE_WAKE
PMIC_ON_REQ: J2.6 TP14.1
POK_1V5_MODULE: J2.5 ; port POK_1V5_MODULE
POK_3V3: J2.9 ; port POK_3V3
POK_5V: J2.7 ; port POK_5V
SATA_RX_N: J2.36 ; port SATA_RX_N
SATA_RX_P: J2.38 ; port SATA_RX_P
SATA_TX_N: J2.42 ; port SATA_TX_N
SATA_TX_P: J2.44 ; port SATA_TX_P
SD3_CD: J2.33 ; port SD3_CD
SD3_CLK: J2.37 ; port SD3_CLK
SD3_CMD: J2.39 ; port SD3_CMD
SD3_DATA0: J2.43 ; port SD3_DATA0
SD3_DATA1: J2.45 ; port SD3_DATA1
SD3_DATA2: J2.47 ; port SD3_DATA2
SD3_DATA3: J2.49 ; port SD3_DATA3
SD3_WP: J2.35 ; port SD3_WP
SYS_POKn: J2.2 ; port SYS_POKn
SYS_RSTn: J2.4 ; port SYS_RSTn
TRD0_N: J3.1 ; port TRD0_N
TRD0_P: J3.3 ; port TRD0_P
TRD1_N: J3.7 ; port TRD1_N
TRD1_P: J3.9 ; port TRD1_P
TRD2_N: J3.2 ; port TRD2_N
TRD2_P: J3.4 ; port TRD2_P
TRD3_N: J3.8 ; port TRD3_N
TRD3_P: J3.10 ; port TRD3_P
UART1_CTS: J2.59 ; port UART1_CTS
UART1_RTS: J2.57 ; port UART1_RTS
UART1_RXD: J2.55 ; port UART1_RXD
UART1_TXD: J2.53 ; port UART1_TXD
UART2_RXD: J2.63 ; port UART2_RXD
UART2_TXD: J2.61 ; port UART2_TXD
UART3_CTS: J3.77 ; port UART3_CTS
UART3_RTS: J3.75 ; port UART3_RTS
UART3_RXD: J3.73 ; port UART3_RXD
UART3_TXD: J3.71 ; port UART3_TXD
UART4_RXD: J2.60 ; port UART4_RXD
UART4_TXD: J2.58 ; port UART4_TXD
UART5_RXD: J2.64 ; port UART5_RXD
UART5_TXD: J2.62 ; port UART5_TXD
USB0_ID: J2.68 ; port USB0_ID
USB0_ID_BUFF_EN: J1.38 ; port USB0_ID_BUFF_EN
USB0_N: J2.73 ; port USB0_N
USB0_P: J2.75 ; port USB0_P
USB0_PWR_EN: J2.74 ; port USB0_PWR_EN
USB1_N: J2.67 ; port USB1_N
USB1_P: J2.69 ; port USB1_P
USB1_PWR_EN: J2.72 ; port USB1_PWR_EN
USB_OC: J2.70 ; port USB_OC
USER_BUTTON: J2.10 ; port USER_BUTTON
USER_LED_BB: J1.82 ; port USER_LED_BB
VID_IN_CSI0_D0: J1.48 ; port VID_IN_CSI0_D0
VID_IN_CSI0_D1: J1.50 ; port VID_IN_CSI0_D1
VID_IN_CSI0_D2: J1.52 ; port VID_IN_CSI0_D2
VID_IN_CSI0_D3: J1.54 ; port VID_IN_CSI0_D3
VID_IN_CSI0_D4: J1.51 ; port VID_IN_CSI0_D4
VID_IN_CSI0_D5: J1.53 ; port VID_IN_CSI0_D5
VID_IN_CSI0_D6: J1.55 ; port VID_IN_CSI0_D6
VID_IN_CSI0_D7: J1.57 ; port VID_IN_CSI0_D7
VID_IN_CSI0_D8: J1.58 ; port VID_IN_CSI0_D8
VID_IN_CSI0_D9: J1.60 ; port VID_IN_CSI0_D9
VID_IN_CSI0_D10: J1.62 ; port VID_IN_CSI0_D10
VID_IN_CSI0_D11: J1.64 ; port VID_IN_CSI0_D11
VID_IN_CSI0_D12: J1.61 ; port VID_IN_CSI0_D12
VID_IN_CSI0_D13: J1.63 ; port VID_IN_CSI0_D13
VID_IN_CSI0_D14: J1.65 ; port VID_IN_CSI0_D14
VID_IN_CSI0_D15: J1.67 ; port VID_IN_CSI0_D15
VID_IN_CSI0_D16: J1.68 ; port VID_IN_CSI0_D16
VID_IN_CSI0_D17: J1.70 ; port VID_IN_CSI0_D17
VID_IN_CSI0_D18: J1.72 ; port VID_IN_CSI0_D18
VID_IN_CSI0_D19: J1.74 ; port VID_IN_CSI0_D19
VID_IN_CSI0_DE: J1.75 ; port VID_IN_CSI0_DE
VID_IN_CSI0_HS: J1.47 ; port VID_IN_CSI0_HS
VID_IN_CSI0_INT: J1.73 ; port VID_IN_CSI0_INT
VID_IN_CSI0_PIXCLK: J1.43 ; port VID_IN_CSI0_PIXCLK
VID_IN_CSI0_RSTn: J1.71 ; port VID_IN_CSI0_RSTn
VID_IN_CSI0_VS: J1.45 ; port VID_IN_CSI0_VS

Not connected (* = marked no-connect by the designer): J1 25* 26* 27* 28* 31* 32* 33* 34* 37* 39* 91* 93* 97* 98* 99* 100*; J2 1* 20* 91* 93* 97* 99*; J3 13* 15* 17* 18* 21* 23* 24* 26* 27* 29* 30* 31* 32* 33* 34* 36* 37* 39* 40* 41* 42* 43* 44* 46* 47* 49* 51* 53* 57* 59* 61* 63* 65* 67* 81* 82* 83* 84* 85* 86* 87* 88* 89* 90* 93* 94* 95* 96* 97* 98* 99* 100*

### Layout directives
net class MIPI_CSI: CSI1_PIXCLK
net class GPIO: CPU_GPIO0_R

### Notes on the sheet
- CONNECTORS
- DESIGN NOTE:
  +VIN must be provided from baseboard to the module. Maximum current 3.6A.
- DESIGN NOTE:
  *1 Be careful, these pins are connected to +3V0_ALWAYS.
- DESIGN NOTE:
  *4 These pins have an internal 100k pull down resistor before RESET.
- DESIGN NOTE:
  *6 These pins use different naming in module and in baseboard schematic. Be sure you set these pins correctly according to the version of the baseboard.
- (Output voltage from BB)
- +VIN = +2.7-5.5 VDC
- DESIGN NOTE:
  *2 This pin must not be left unconnected (See Power Sequencing Page 16).
- DESIGN NOTE:
  *5 These pins are set as output with unknown state before the reset. See Table 103 page 167 in IMX6DQAEC.
- DESIGN NOTE:
  Optional: If ON-OFF operation is required 3V0_ALWAYS source is needed. Testing required.
- DESIGN NOTE:
  Connector J3 is optional - signals on this connector are not required in the booting process.
- level 5V
- *1
- (near J2) *2
- Def: Input PD
- *6
- *4
- (near J2) *4
- (near J3) *4
- Def: Output low
- DESIGN NOTE:
  +3V3 must be provided from baseboard to the module. Typical current 700mA.
- DESIGN NOTE:
  +2V5 required current 350mA
- Optional in future? (Output from BB)
- *5
- Def: Output high
- DESIGN NOTE:
  +5V must be provided from baseboard to the module. Typical current 300mA.
- LAYOUT NOTE:
  If 1.5mm standoff Board to Board connector is used, do not place any components under the module.
- DESIGN NOTE:
  Mating connector default: DF40C-100DP-0.4V(51)
  http://www.digikey.com/product-detail/en/DF40C-100DP-0.4V%2851%29/H11614TR-ND/1969475
- DESIGN NOTE:
  Use one of the options to fit series resistors according to the picture below.
- CPU GPIO0_R
- CPU PIXCLK
- SYS HDR
- CSI CON
- DESIGN NOTE:
  Maximum current for the board to board connector is 0.3A per contact.
- OPTION 1 (default):
- CPU GPIO0_R to SYS HDR
- 0R
- CPU PIXCLK to CSI CON
- OPTION 2:
- CPU GPIO0_R to CSI CON
- R43
- R35
- Free for personal and commercial use.
- R42
- Variant:
- Checked by

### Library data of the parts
C1-C3 C16 C231 C232 = C1608X5R0J226M080AC: CAP CER 22UF 6.3V 20% X5R 0603; Manufacturer: TDK Corporation; Capacitance: 22µF; .Creator: MM
C4-C7 C12-C15 = C1005X5R1H104K: as C69 on sheet [07] - PCIE MINI
J1-J3 = DF40C-100DS-0.4V(51)_v1.1: CONN RCPT 100POS 0.4MM SMD GOLD; Manufacturer: Hirose Electric Co Ltd; Connector Type: Receptacle, Center Strip Contacts; Number of Positions: 100; Pitch: 0.016" (0.40mm); Mated Stacking Heights: 1.5mm; .Creator: MM
R35 R42 R43 = RC0402FR-0722RL: RES 22.0 OHM 1/16W 1% 0402 SMD; Manufacturer: Yageo; Resistance (Ohms): 22; Power (Watts): 0.063W, 1/16W; .Checked PCB: used; Temperature Coefficient: ±100ppm/°C
TP7 TP8 TP11 TP14 = TP_25MILC: Test Point 25mil

## Sheet [10] - SATA, CSI.SchDoc
size A3; DocumentNumber: 10; SheetNumber: 10; SheetTotal: 18
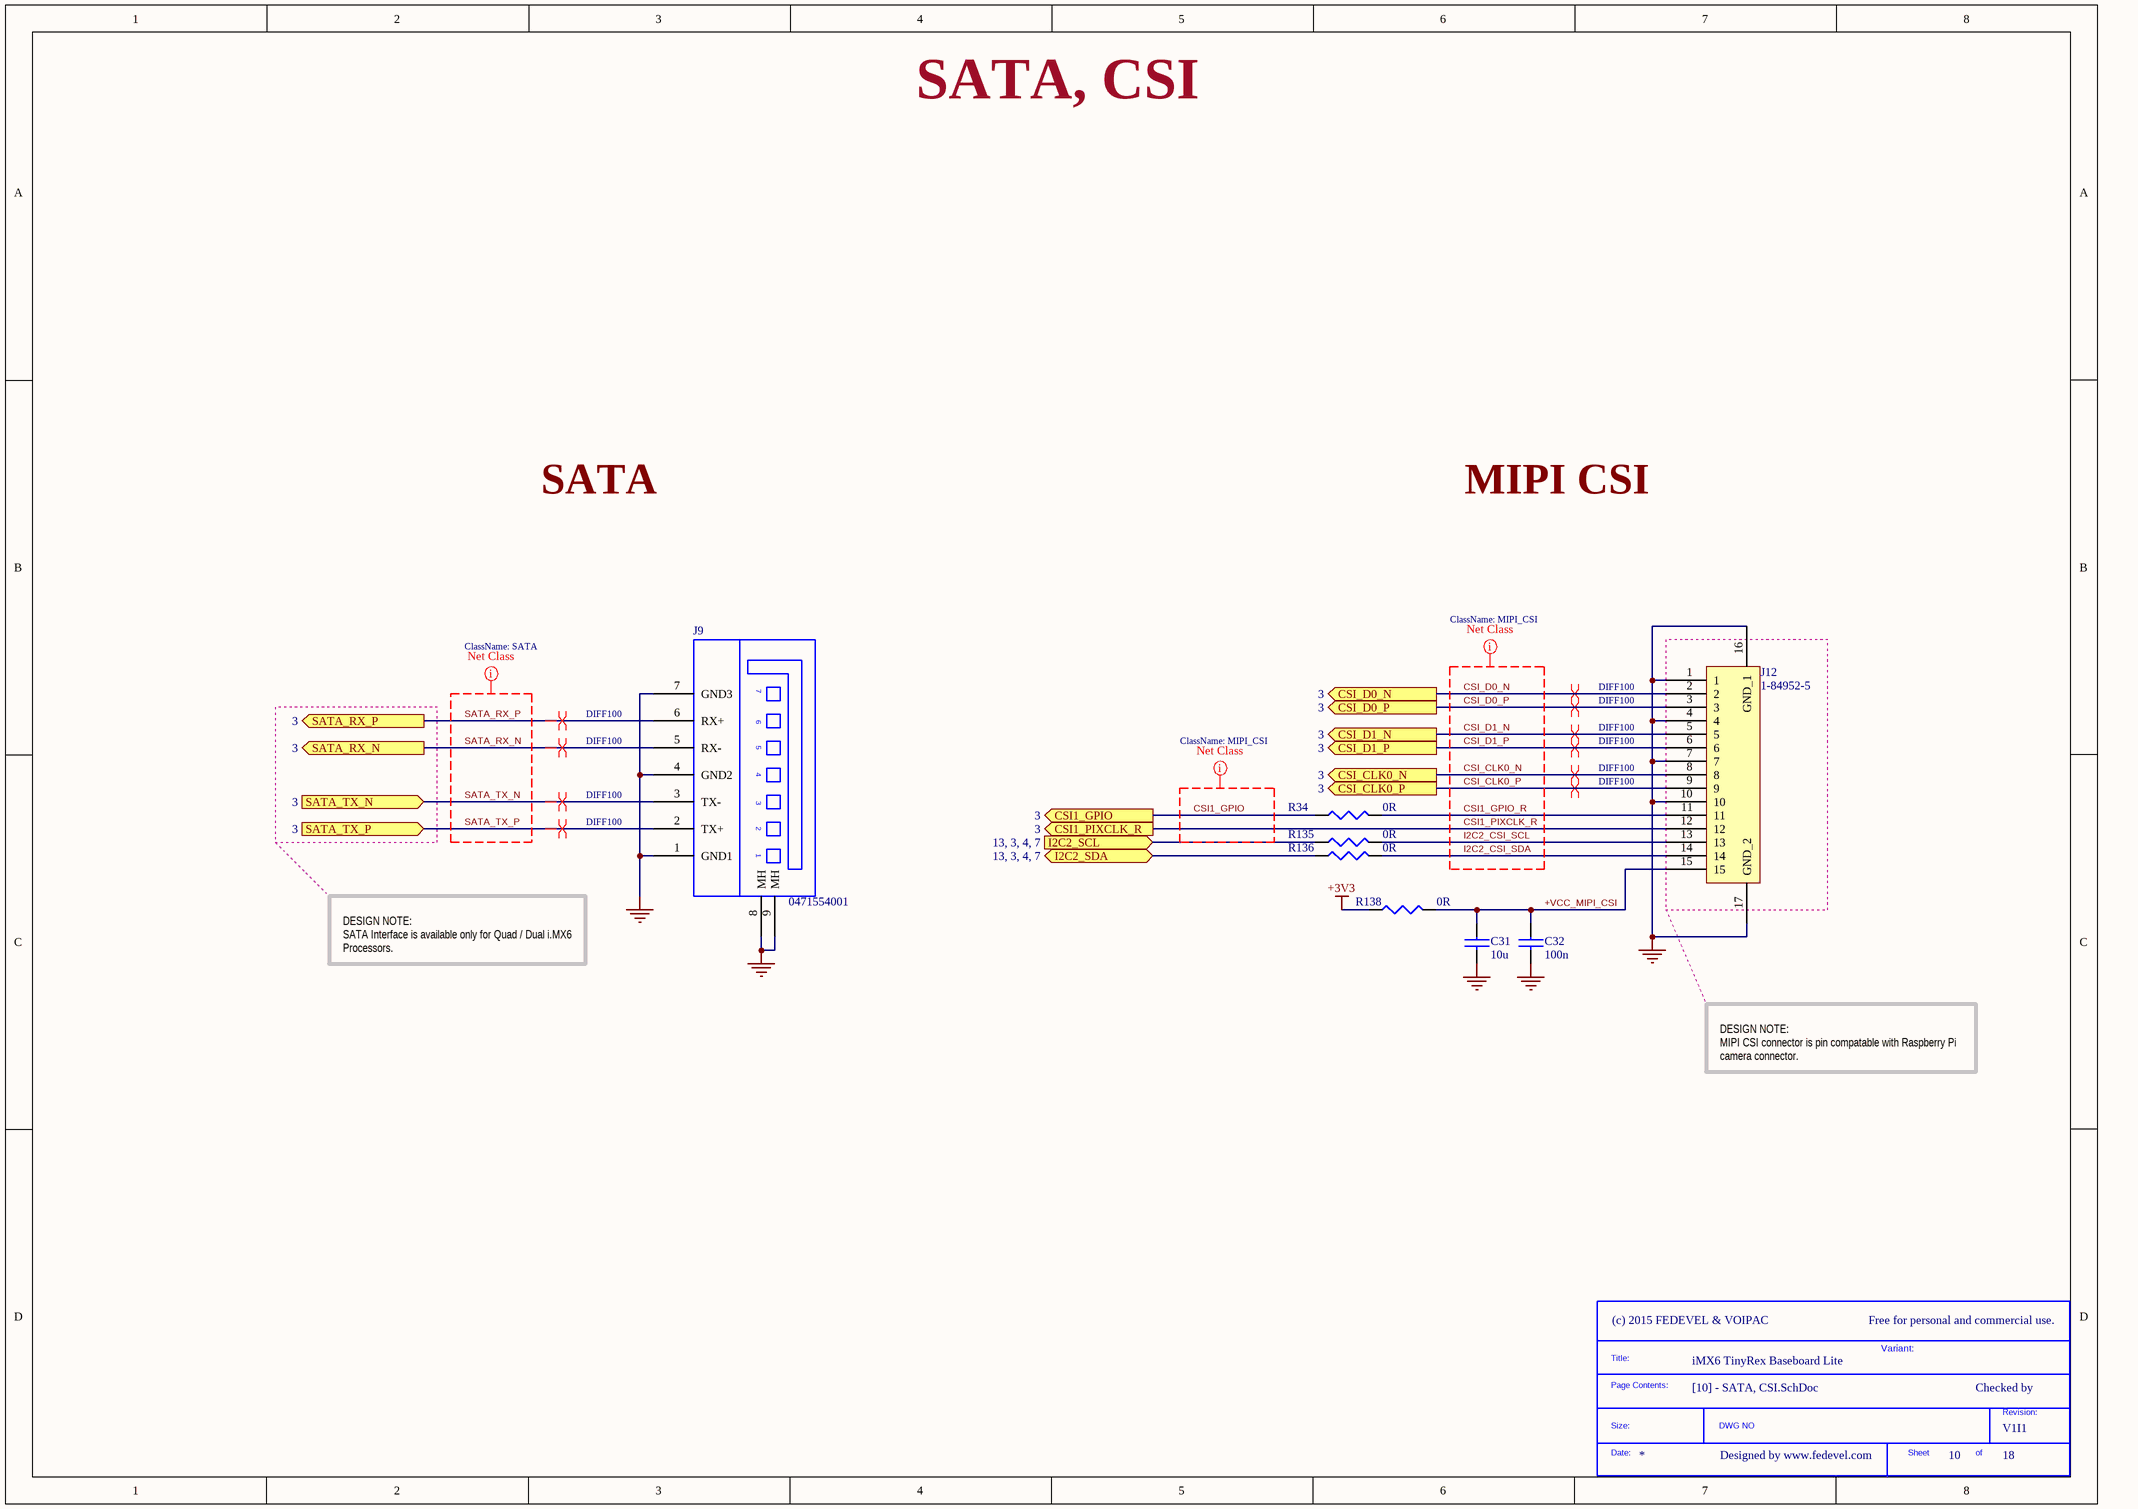
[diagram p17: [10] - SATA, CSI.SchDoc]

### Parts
(Parts that share a designator on the sheet are numbered #1, #2 ... from top to bottom, then left to right.)
*#12  SDTitleBlock  (value not drawn)  (graphical)
C31  10u  [C0603]
C32  100n  [C0402]
J9  0471554001  [SATA_VERTICAL]
J12  1-84952-5  [ZIF_RA_BOTTOM_15x1mm]
R34  0R  [R0402]
R135  0R  [R0402]
R136  0R  [R0402]
R138  0R  [R0402]

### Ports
CSI1_GPIO (out, see 3), CSI1_PIXCLK_R (out, see 3), CSI_CLK0_N (out, see 3), CSI_CLK0_P (out, see 3), CSI_D0_N (out, see 3), CSI_D0_P (out, see 3), CSI_D1_N (out, see 3), CSI_D1_P (out, see 3), I2C2_SCL (see 13, 3, 4, 7), I2C2_SDA (bidir, see 13, 3, 4, 7), SATA_RX_N (out, see 3), SATA_RX_P (out, see 3), SATA_TX_N (in, see 3), SATA_TX_P (in, see 3)

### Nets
+3V3: R138.1
GND: C31.2 C32.2 J9.1(GND1) J9.4(GND2) J9.7(GND3) J9.8(MH) J9.9(MH) J12.1 J12.4 J12.7 J12.10 J12.16(GND_1) J12.17(GND_2)
+VCC_MIPI_CSI: C31.1 C32.1 J12.15 R138.2
CSI1_GPIO: R34.2 ; port CSI1_GPIO
CSI1_GPIO_R: J12.11 R34.1
CSI1_PIXCLK_R: J12.12 ; port CSI1_PIXCLK_R
CSI_CLK0_N: J12.8 ; port CSI_CLK0_N
CSI_CLK0_P: J12.9 ; port CSI_CLK0_P
CSI_D0_N: J12.2 ; port CSI_D0_N
CSI_D0_P: J12.3 ; port CSI_D0_P
CSI_D1_N: J12.5 ; port CSI_D1_N
CSI_D1_P: J12.6 ; port CSI_D1_P
I2C2_CSI_SCL: J12.13 R135.1
I2C2_CSI_SDA: J12.14 R136.1
I2C2_SCL: R135.2 ; port I2C2_SCL
I2C2_SDA: R136.2 ; port I2C2_SDA
SATA_RX_N: J9.5(RX-) ; port SATA_RX_N
SATA_RX_P: J9.6(RX+) ; port SATA_RX_P
SATA_TX_N: J9.3(TX-) ; port SATA_TX_N
SATA_TX_P: J9.2(TX+) ; port SATA_TX_P

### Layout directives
differential pair; net class DIFF100: CSI_CLK0_N, CSI_CLK0_P, CSI_D0_N, CSI_D0_P, CSI_D1_N, CSI_D1_P, SATA_RX_N, SATA_RX_P, SATA_TX_N, SATA_TX_P
net class SATA: SATA_RX_N, SATA_RX_P, SATA_TX_N, SATA_TX_P
net class MIPI_CSI: CSI1_GPIO, CSI1_GPIO_R, CSI1_PIXCLK_R, CSI_CLK0_N, CSI_CLK0_P, CSI_D0_N, CSI_D0_P, CSI_D1_N, CSI_D1_P, I2C2_CSI_SCL, I2C2_CSI_SDA

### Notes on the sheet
- SATA, CSI
- SATA
- MIPI CSI
- DESIGN NOTE:
  SATA Interface is available only for Quad / Dual i.MX6 Processors.
- DESIGN NOTE:
  MIPI CSI connector is pin compatable with Raspberry Pi camera connector.
- Free for personal and commercial use.
- Variant:
- Checked by
- Designed by www.fedevel.com

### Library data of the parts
C31 = C1608X5R0J106M: as C20 on sheet [07] - PCIE MINI
C32 = C1005X5R1H104K: as C69 on sheet [07] - PCIE MINI
J9 = 0471554001: CONN SATA HDR 7POS PCB VERT; Manufacturer: Molex Inc; Connector Style: Header, Shrouded; Number of Positions: 7; .Checked PCB: used
J12 = 1-84952-5: CONN FPC BOTTOM 15POS 1.00MM R/A; Manufacturer: TE Connectivity; Connector/Contact Type: Contacts, Bottom; Number of Positions: 15; Pitch: 0.039" (1.00mm); FFC, FCB Thickness: 0.30mm; Locking Feature: Slide Lock; Cable End Type: Straight; Actuator Material: Polyamide (PA), Nylon, Glass Filled; Voltage Rating: 200V; Material Flammability Rating: UL94 V-0; Current Rating: 1A; .Creator: MM
R34 R135 R136 R138 = RC0402JR-070RL: as R22 on sheet [07] - PCIE MINI

## Sheet [11] - SD CARD, BUFFERS.SchDoc
size A3; DocumentNumber: 11; SheetNumber: 11; SheetTotal: 18
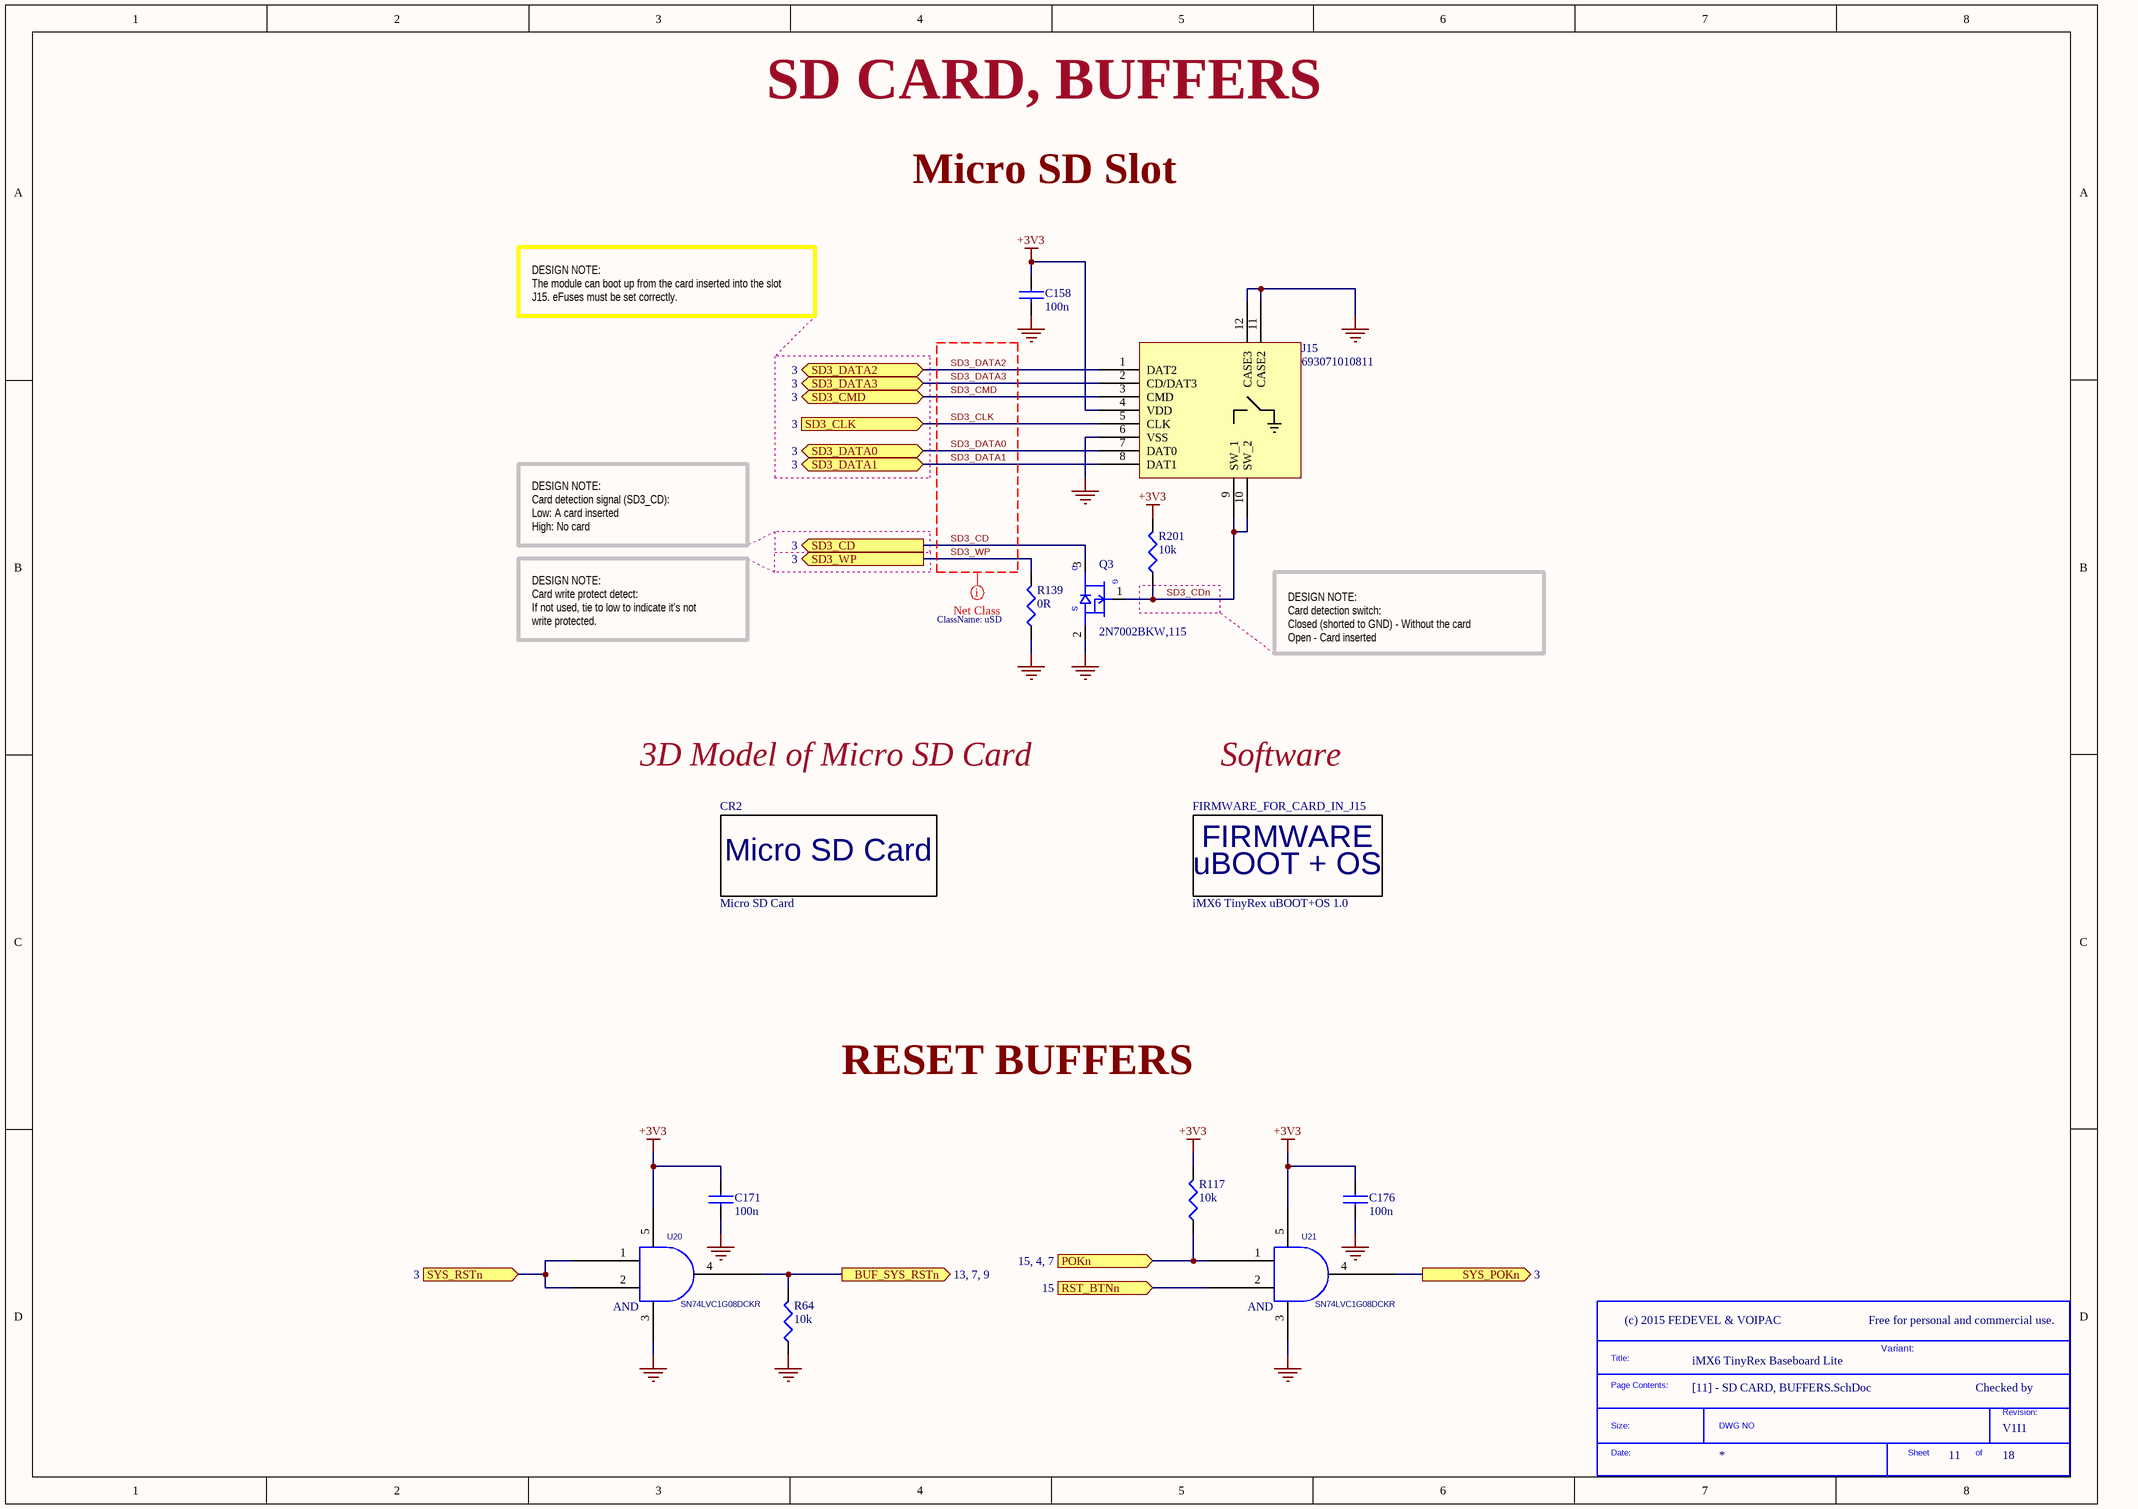
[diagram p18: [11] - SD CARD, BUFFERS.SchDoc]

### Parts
(Parts that share a designator on the sheet are numbered #1, #2 ... from top to bottom, then left to right.)
*#13  SDTitleBlock  (value not drawn)  (graphical)
C158  100n  [C0402]
C171  100n  [C0402]
C176  100n  [C0402]
CR2  Micro SD Card  [Micro_SD_card]  (no BOM)
FIRMWARE_FOR_CARD_IN_J15  iMX6 TinyRex uBOOT+OS 1.0  (mechanical)
J15  693071010811  [693071010811]
Q3  2N7002BKW,115  [SC70_SOT323]
R64  10k  [R0402]
R117  10k  [R0402]
R139  0R  [R0402]
R201  10k  [R0402]
U20  SN74LVC1G08DCKR  [SC70_5]
U21  SN74LVC1G08DCKR  [SC70_5]

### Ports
BUF_SYS_RSTn (see 13, 7, 9), POKn (see 15, 4, 7), RST_BTNn (in, see 15), SD3_CD (out, see 3), SD3_CLK (in, see 3), SD3_CMD (bidir, see 3), SD3_DATA0 (bidir, see 3), SD3_DATA1 (bidir, see 3), SD3_DATA2 (bidir, see 3), SD3_DATA3 (bidir, see 3), SD3_WP (out, see 3), SYS_POKn (out, see 3), SYS_RSTn (in, see 3)

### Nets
+3V3: C158.1 C171.1 C176.1 J15.4(VDD) R117.2 R201.2 U20.5(VCC) U21.5(VCC)
GND: C158.2 C171.2 C176.2 J15.6(VSS) J15.11(CASE2) J15.12(CASE3) Q3.2(SOURCE) R64.1 R139.1 U20.3(GND) U21.3(GND)
BUF_SYS_RSTn: R64.2 U20.4(Y) ; port BUF_SYS_RSTn
POKn: R117.1 U21.1(A) ; port POKn
RST_BTNn: U21.2(B) ; port RST_BTNn
SD3_CD: Q3.3(DRAIN) ; port SD3_CD
SD3_CDn: J15.9(SW_1) J15.10(SW_2) Q3.1(GATE) R201.1
SD3_CLK: J15.5(CLK) ; port SD3_CLK
SD3_CMD: J15.3(CMD) ; port SD3_CMD
SD3_DATA0: J15.7(DAT0) ; port SD3_DATA0
SD3_DATA1: J15.8(DAT1) ; port SD3_DATA1
SD3_DATA2: J15.1(DAT2) ; port SD3_DATA2
SD3_DATA3: J15.2(CD/DAT3) ; port SD3_DATA3
SD3_WP: R139.2 ; port SD3_WP
SYS_POKn: U21.4(Y) ; port SYS_POKn
SYS_RSTn: U20.1(A) U20.2(B) ; port SYS_RSTn

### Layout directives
net class uSD: SD3_CD, SD3_CLK, SD3_CMD, SD3_DATA0, SD3_DATA1, SD3_DATA2, SD3_DATA3, SD3_WP

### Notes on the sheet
- SD CARD, BUFFERS
- Micro SD Slot
- DESIGN NOTE:
  The module can boot up from the card inserted into the slot J15. eFuses must be set correctly.
- DESIGN NOTE:
  Card detection signal (SD3_CD):
  Low: A card inserted
  High: No card
- DESIGN NOTE:
  Card write protect detect:
  If not used, tie to low to indicate it's not write protected.
- DESIGN NOTE:
  Card detection switch:
  Closed (shorted to GND) - Without the card
  Open - Card inserted
- 3D Model of Micro SD Card
- Software
- RESET BUFFERS
- Free for personal and commercial use.
- Variant:
- Checked by

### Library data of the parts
C158 C171 C176 = C1005X5R1H104K: as C69 on sheet [07] - PCIE MINI
CR2 = Card_Micro_SD: Card Micro SD; .Creator: MM
FIRMWARE_FOR_CARD_IN_J15 = FIRMWARE_iMX6_TinyRex_uBOOT_OS 1.0: .Creator: MM
J15 = 693071010811: CONN MICRO SD 8 POS SMD; Manufacturer: Wurth Electronics Inc; Card Type: Secure Digital - microSD™; Number of Positions: 9 (8 + 1); Connector Type: Connector and Ejector; Insertion, Removal Method: Push In, Push Out; .Creator: MM; .Checked PCB: used
Q3 = 2N7002BKW,115: as Q9 on sheet [09] - USB
R64 R117 R201 = RC0402FR-0710KL: as R10 on sheet [07] - PCIE MINI
R139 = RC0402JR-070RL: as R22 on sheet [07] - PCIE MINI
U20 U21 = SN74LVC1G08DCKR: as U14 on sheet [09] - USB

## Sheet [16] - DOC, POWER SEQUENCING.SchDoc
size A2; DocumentNumber: 16; SheetNumber: 16; SheetTotal: 18
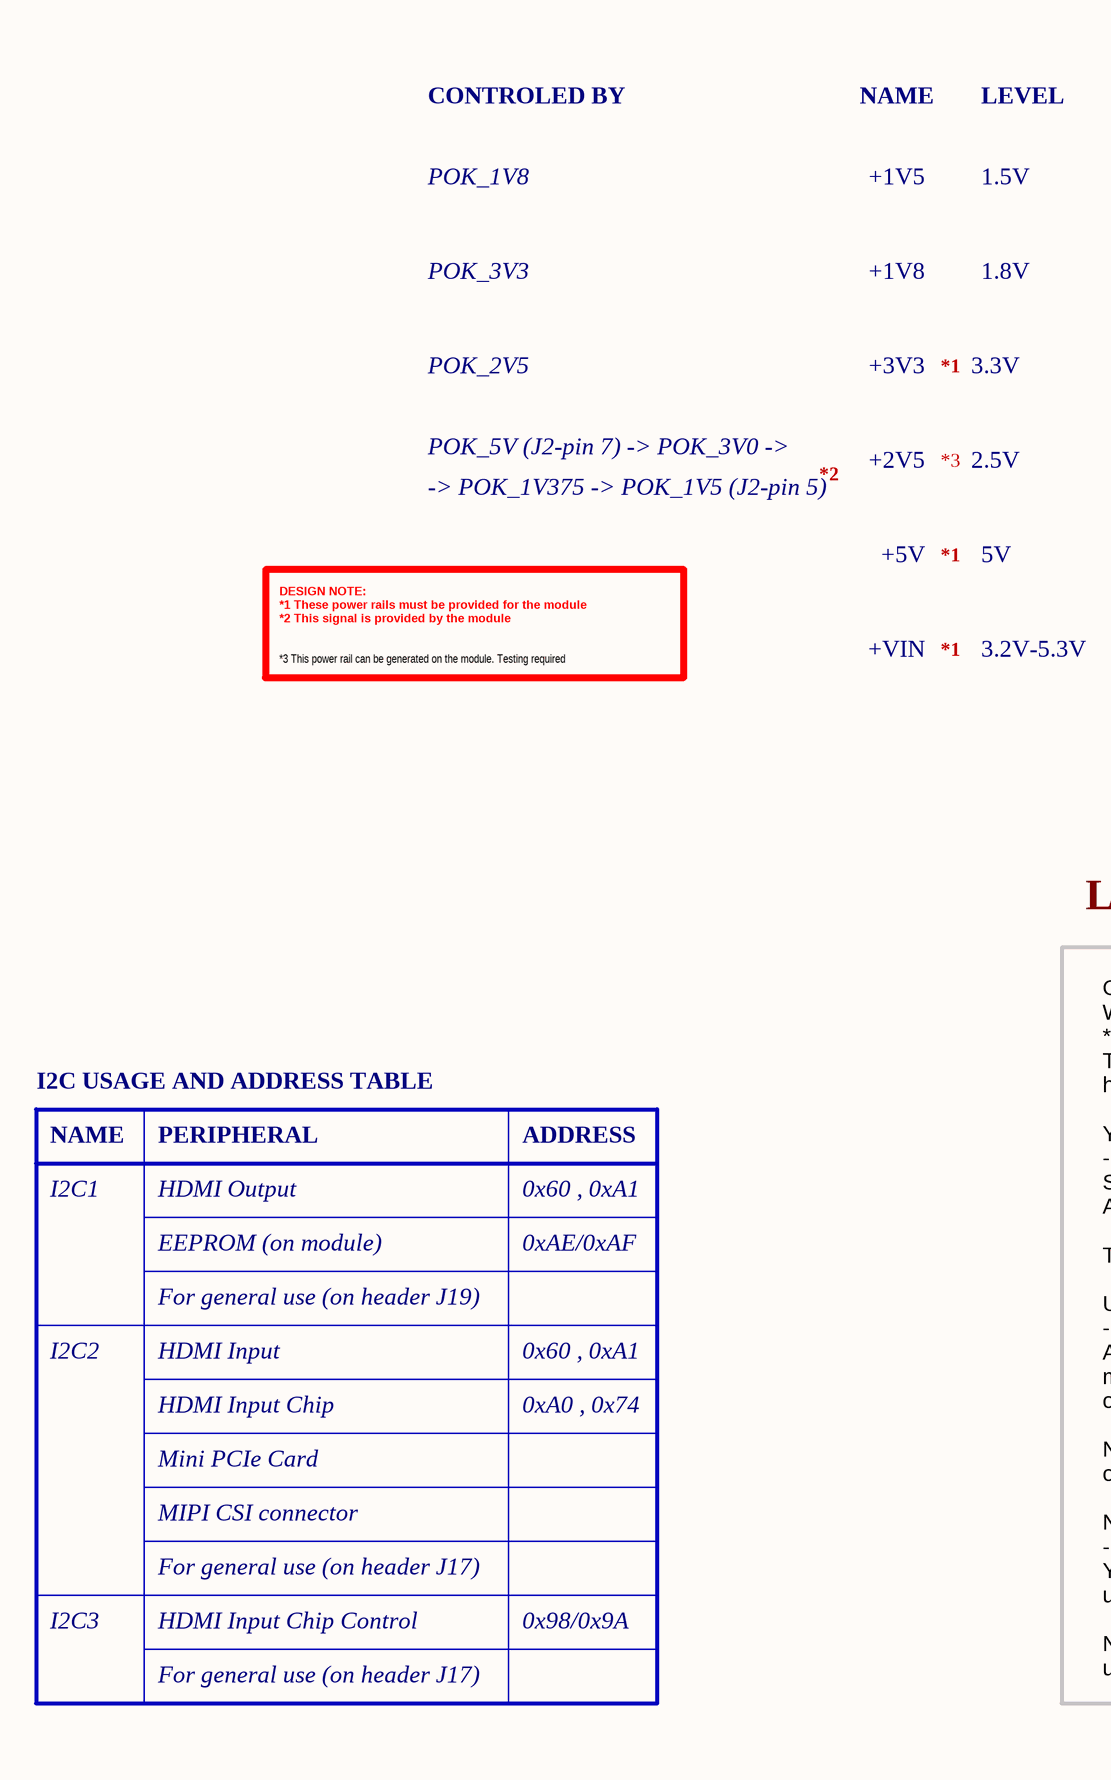
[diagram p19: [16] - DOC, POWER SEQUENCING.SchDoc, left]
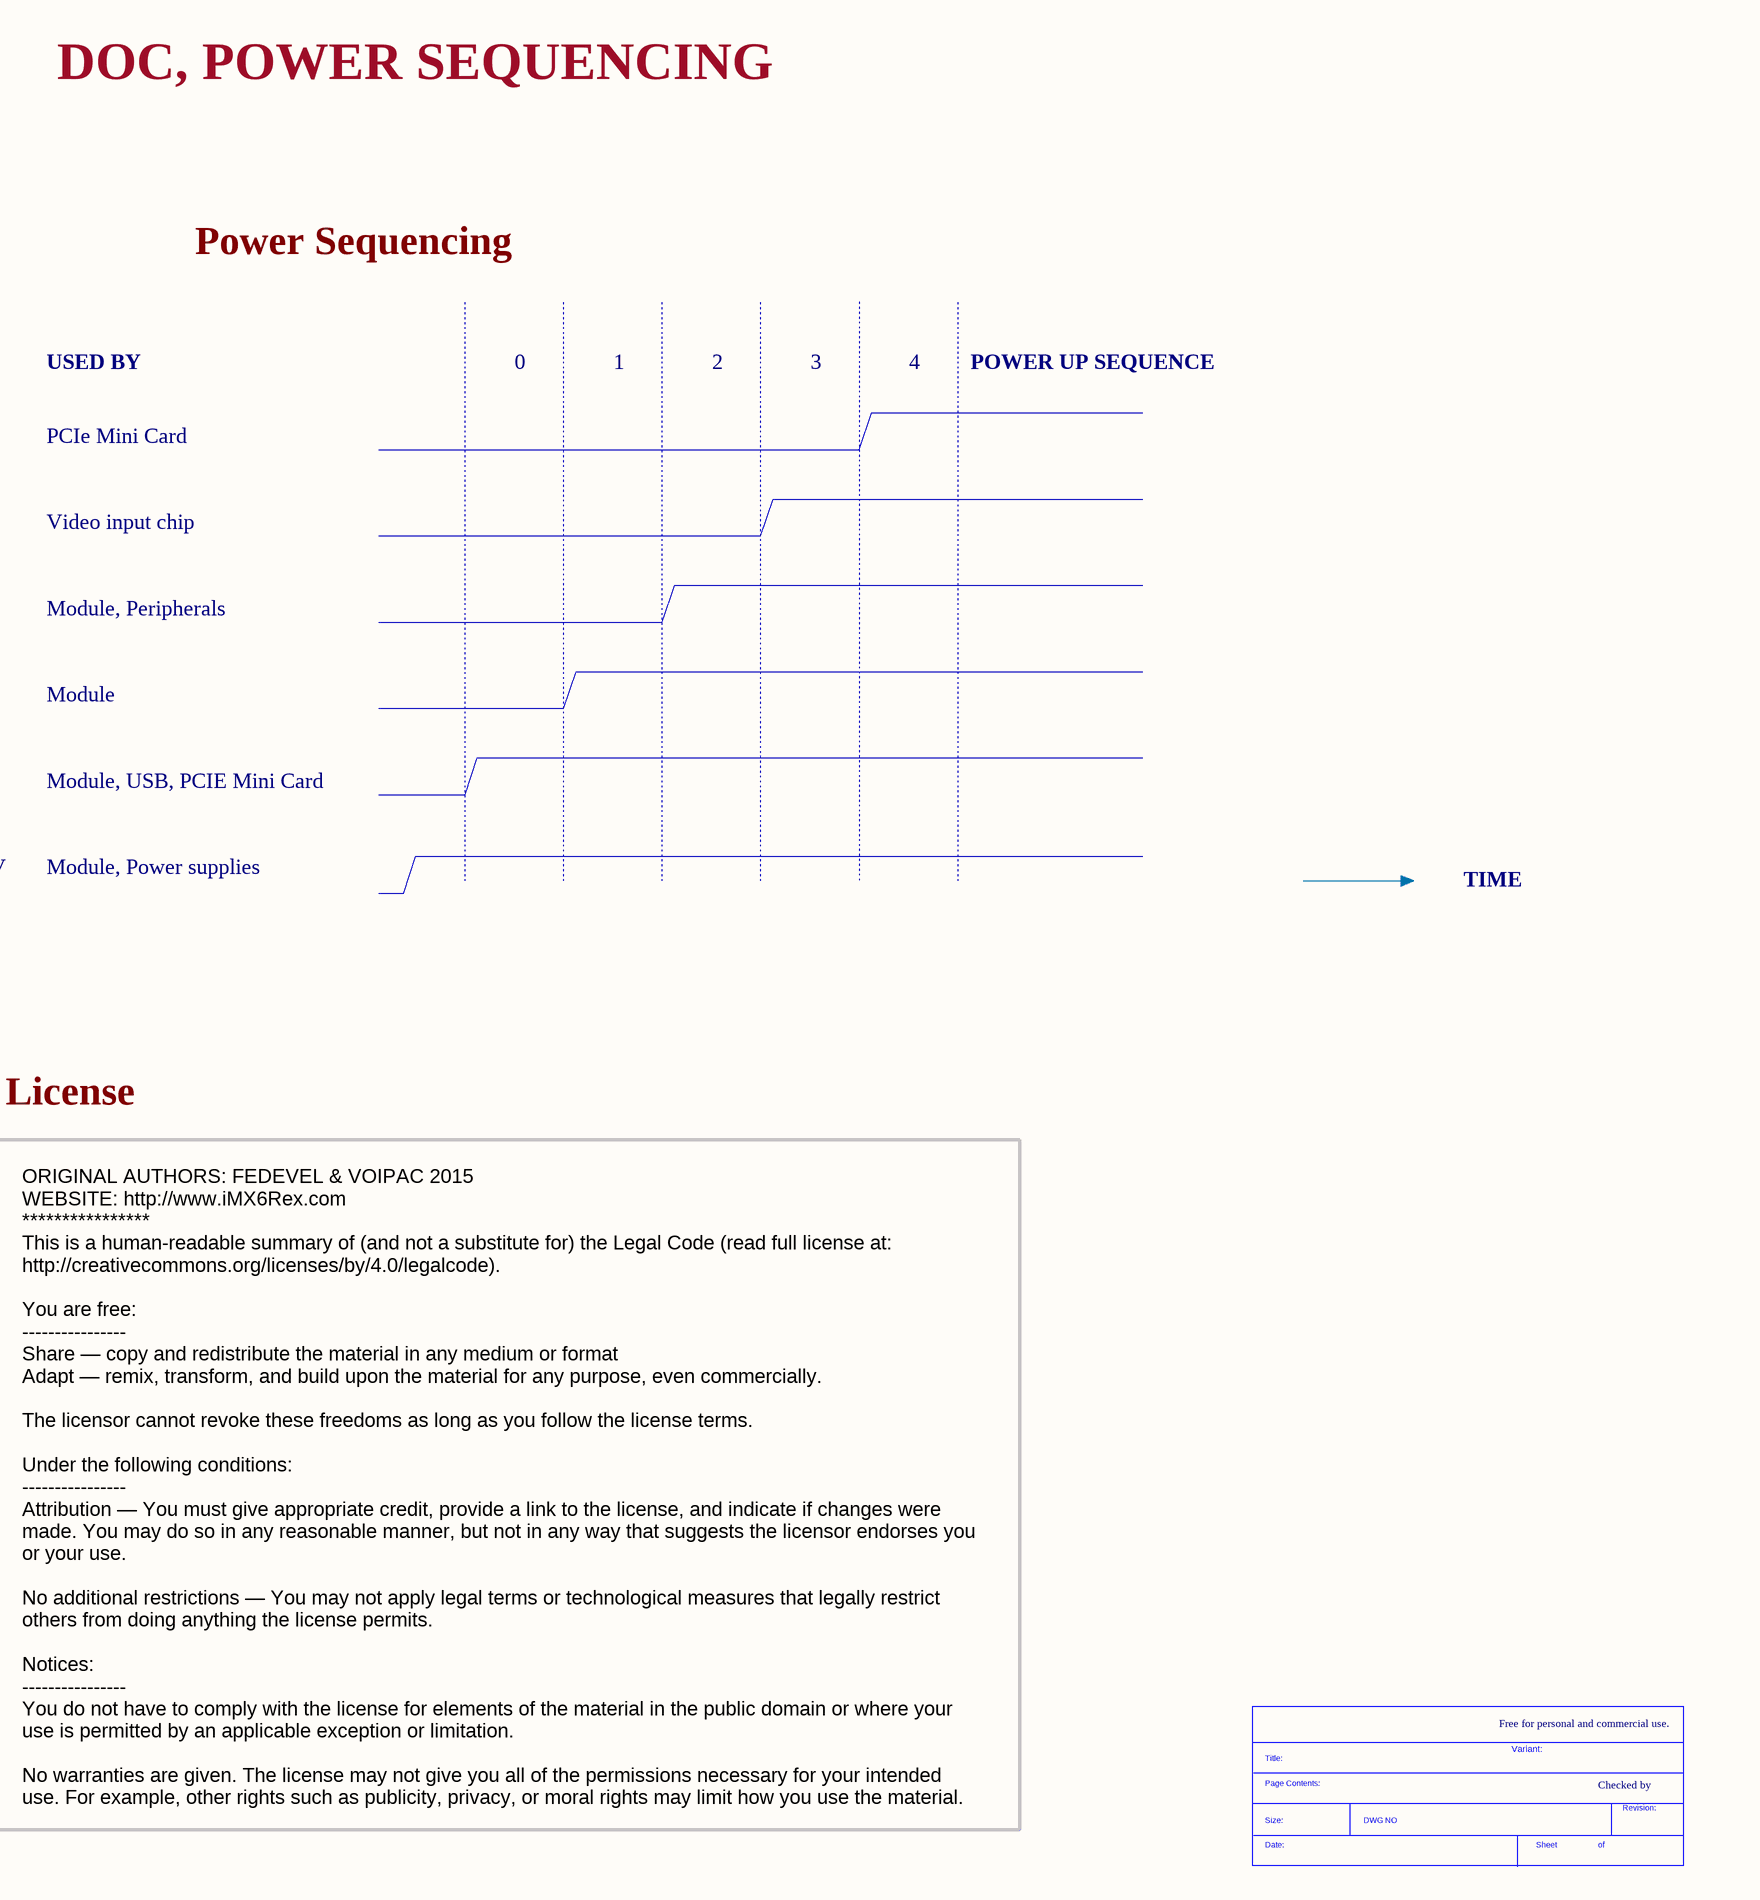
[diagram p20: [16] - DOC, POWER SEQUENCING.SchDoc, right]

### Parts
(Parts that share a designator on the sheet are numbered #1, #2 ... from top to bottom, then left to right.)
*#14  SDTitleBlock  (value not drawn)  (graphical)

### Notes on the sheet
- DOC, POWER SEQUENCING
- Power Sequencing
- CONTROLED BY
- NAME
- LEVEL
- USED BY
- 0
- 1
- 2
- 3
- 4
- POWER UP SEQUENCE
- POK_1V8
- +1V5
- 1.5V
- PCIe Mini Card
- POK_3V3
- +1V8
- 1.8V
- Video input chip
- POK_2V5
- +3V3
- *1
- 3.3V
- Module, Peripherals
- POK_5V (J2-pin 7) -> POK_3V0 ->
- *2
- *3
- -> POK_1V375 -> POK_1V5 (J2-pin 5)
- +2V5
- 2.5V
- Module
- +5V
- 5V
- Module, USB, PCIE Mini Card
- DESIGN NOTE:
  *1 These power rails must be provided for the module
  *2 This signal is provided by the module
- +VIN
- 3.2V-5.3V
- Module, Power supplies
- *3 This power rail can be generated on the module. Testing required
- TIME
- License
- I2C USAGE AND ADDRESS TABLE
- I2C1
- PERIPHERAL
- HDMI Output
- ADDRESS
- 0x60 , 0xA1
- EEPROM (on module)
- 0xAE/0xAF
- For general use (on header J19)
- I2C2
- HDMI Input
- Mini PCIe Card
- HDMI Input Chip
- 0xA0 , 0x74
- MIPI CSI connector
- For general use (on header J17)
- Free for personal and commercial use.
- I2C3
- HDMI Input Chip Control
- 0x98/0x9A
- Variant:
- Checked by
- ORIGINAL AUTHORS: FEDEVEL & VOIPAC 2015
  WEBSITE: http://www.iMX6Rex.com
  ****************
  This is a human-readable summary of (and not a substitute for) the Legal Code (read full license at:
  http://creativecommons.org/licenses/by/4.0/legalcode).
  You are free:
  ----------------
  Share — copy and redistribute the material in any medium or format
  Adapt — remix, transform, and build upon the material for any purpose, even commercially.
  The licensor cannot revoke these freedoms as long as you follow the license terms.
  Under the following conditions:
  ----------------
  Attribution — You must give appropriate credit, provide a link to the license, and indicate if changes were made. You may do so in any reasonable manner, but not in any way that suggests the licensor endorses you or your use.
  No additional restrictions — You may not apply legal terms or technological measures that legally restrict others from doing anything the license permits.
  Notices:
  ----------------
  You do not have to comply with the license for elements of the material in the public domain or where your use is permitted by an applicable exception or limitation.
  No warranties are given. The license may not give you all of the permissions necessary for your intended use. For example, other rights such as publicity, privacy, or moral rights may limit how you use the material.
